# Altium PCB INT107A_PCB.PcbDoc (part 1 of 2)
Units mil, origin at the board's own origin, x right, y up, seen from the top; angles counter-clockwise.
Board outline 2300 x 3400 mil, 4 copper layers (Top Layer, Layer 2 GND, Layer 3 PWR, Bottom Layer), stack 61.634 mil thick; 160 components, 94 nets, 421 pads, 133 vias.
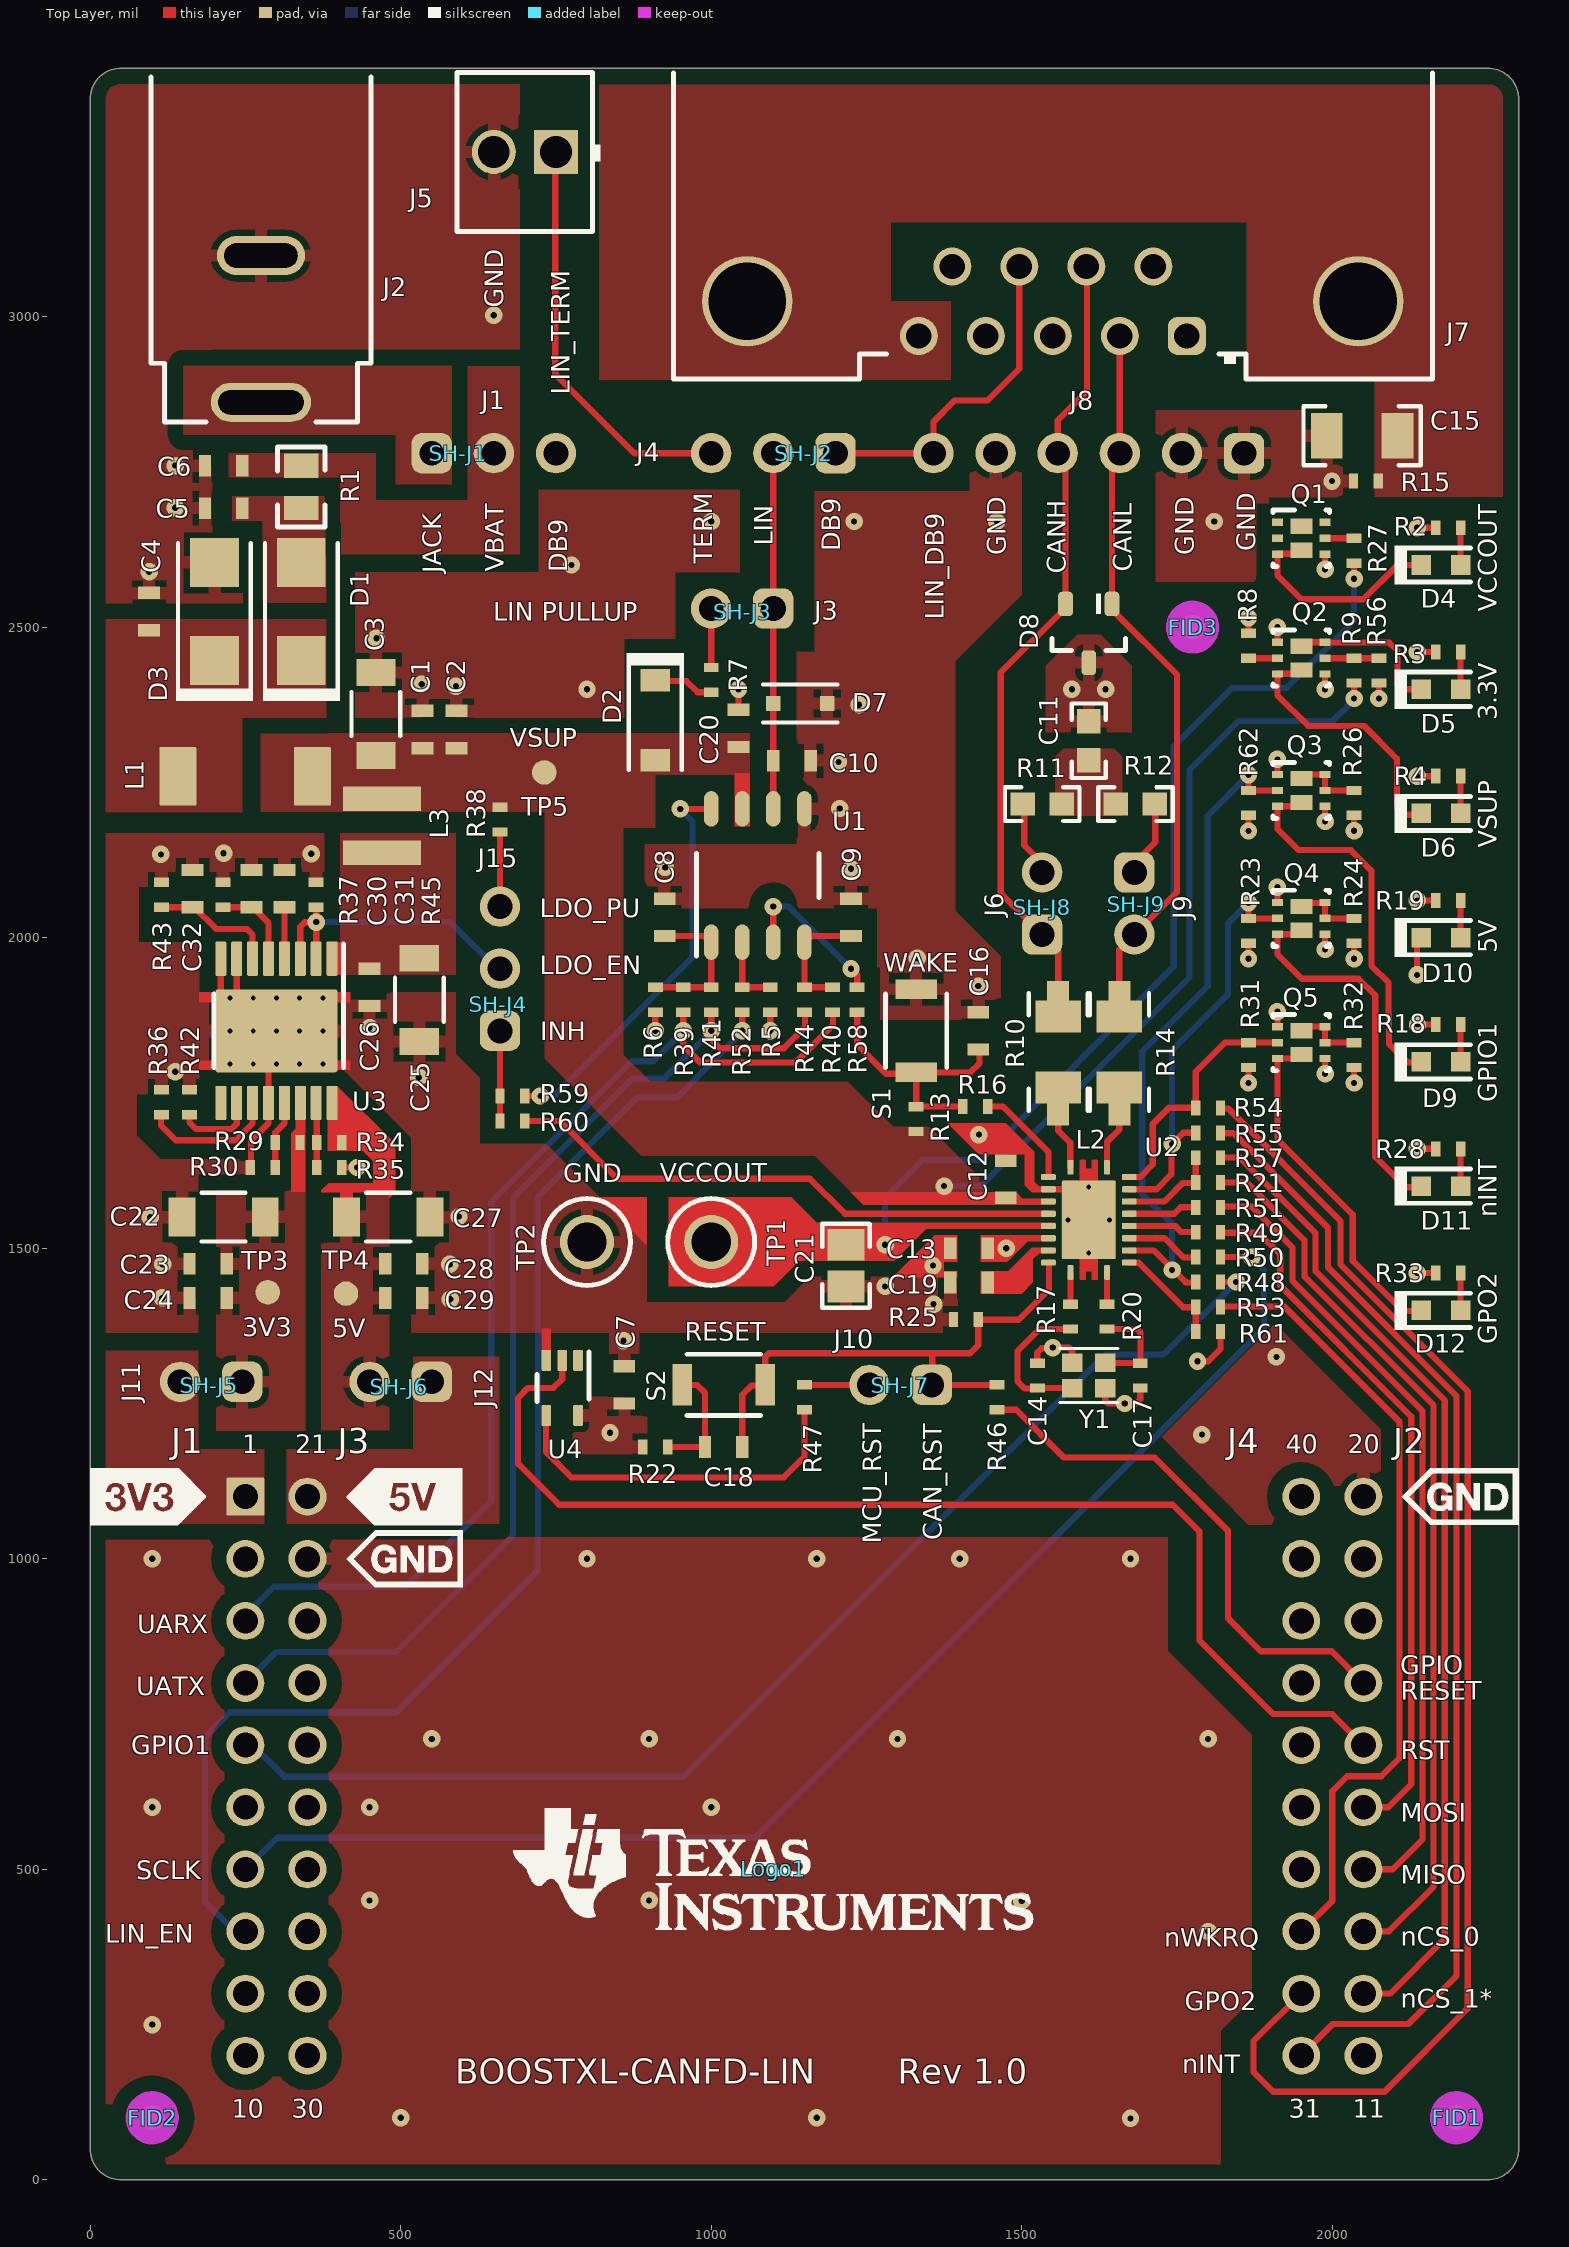
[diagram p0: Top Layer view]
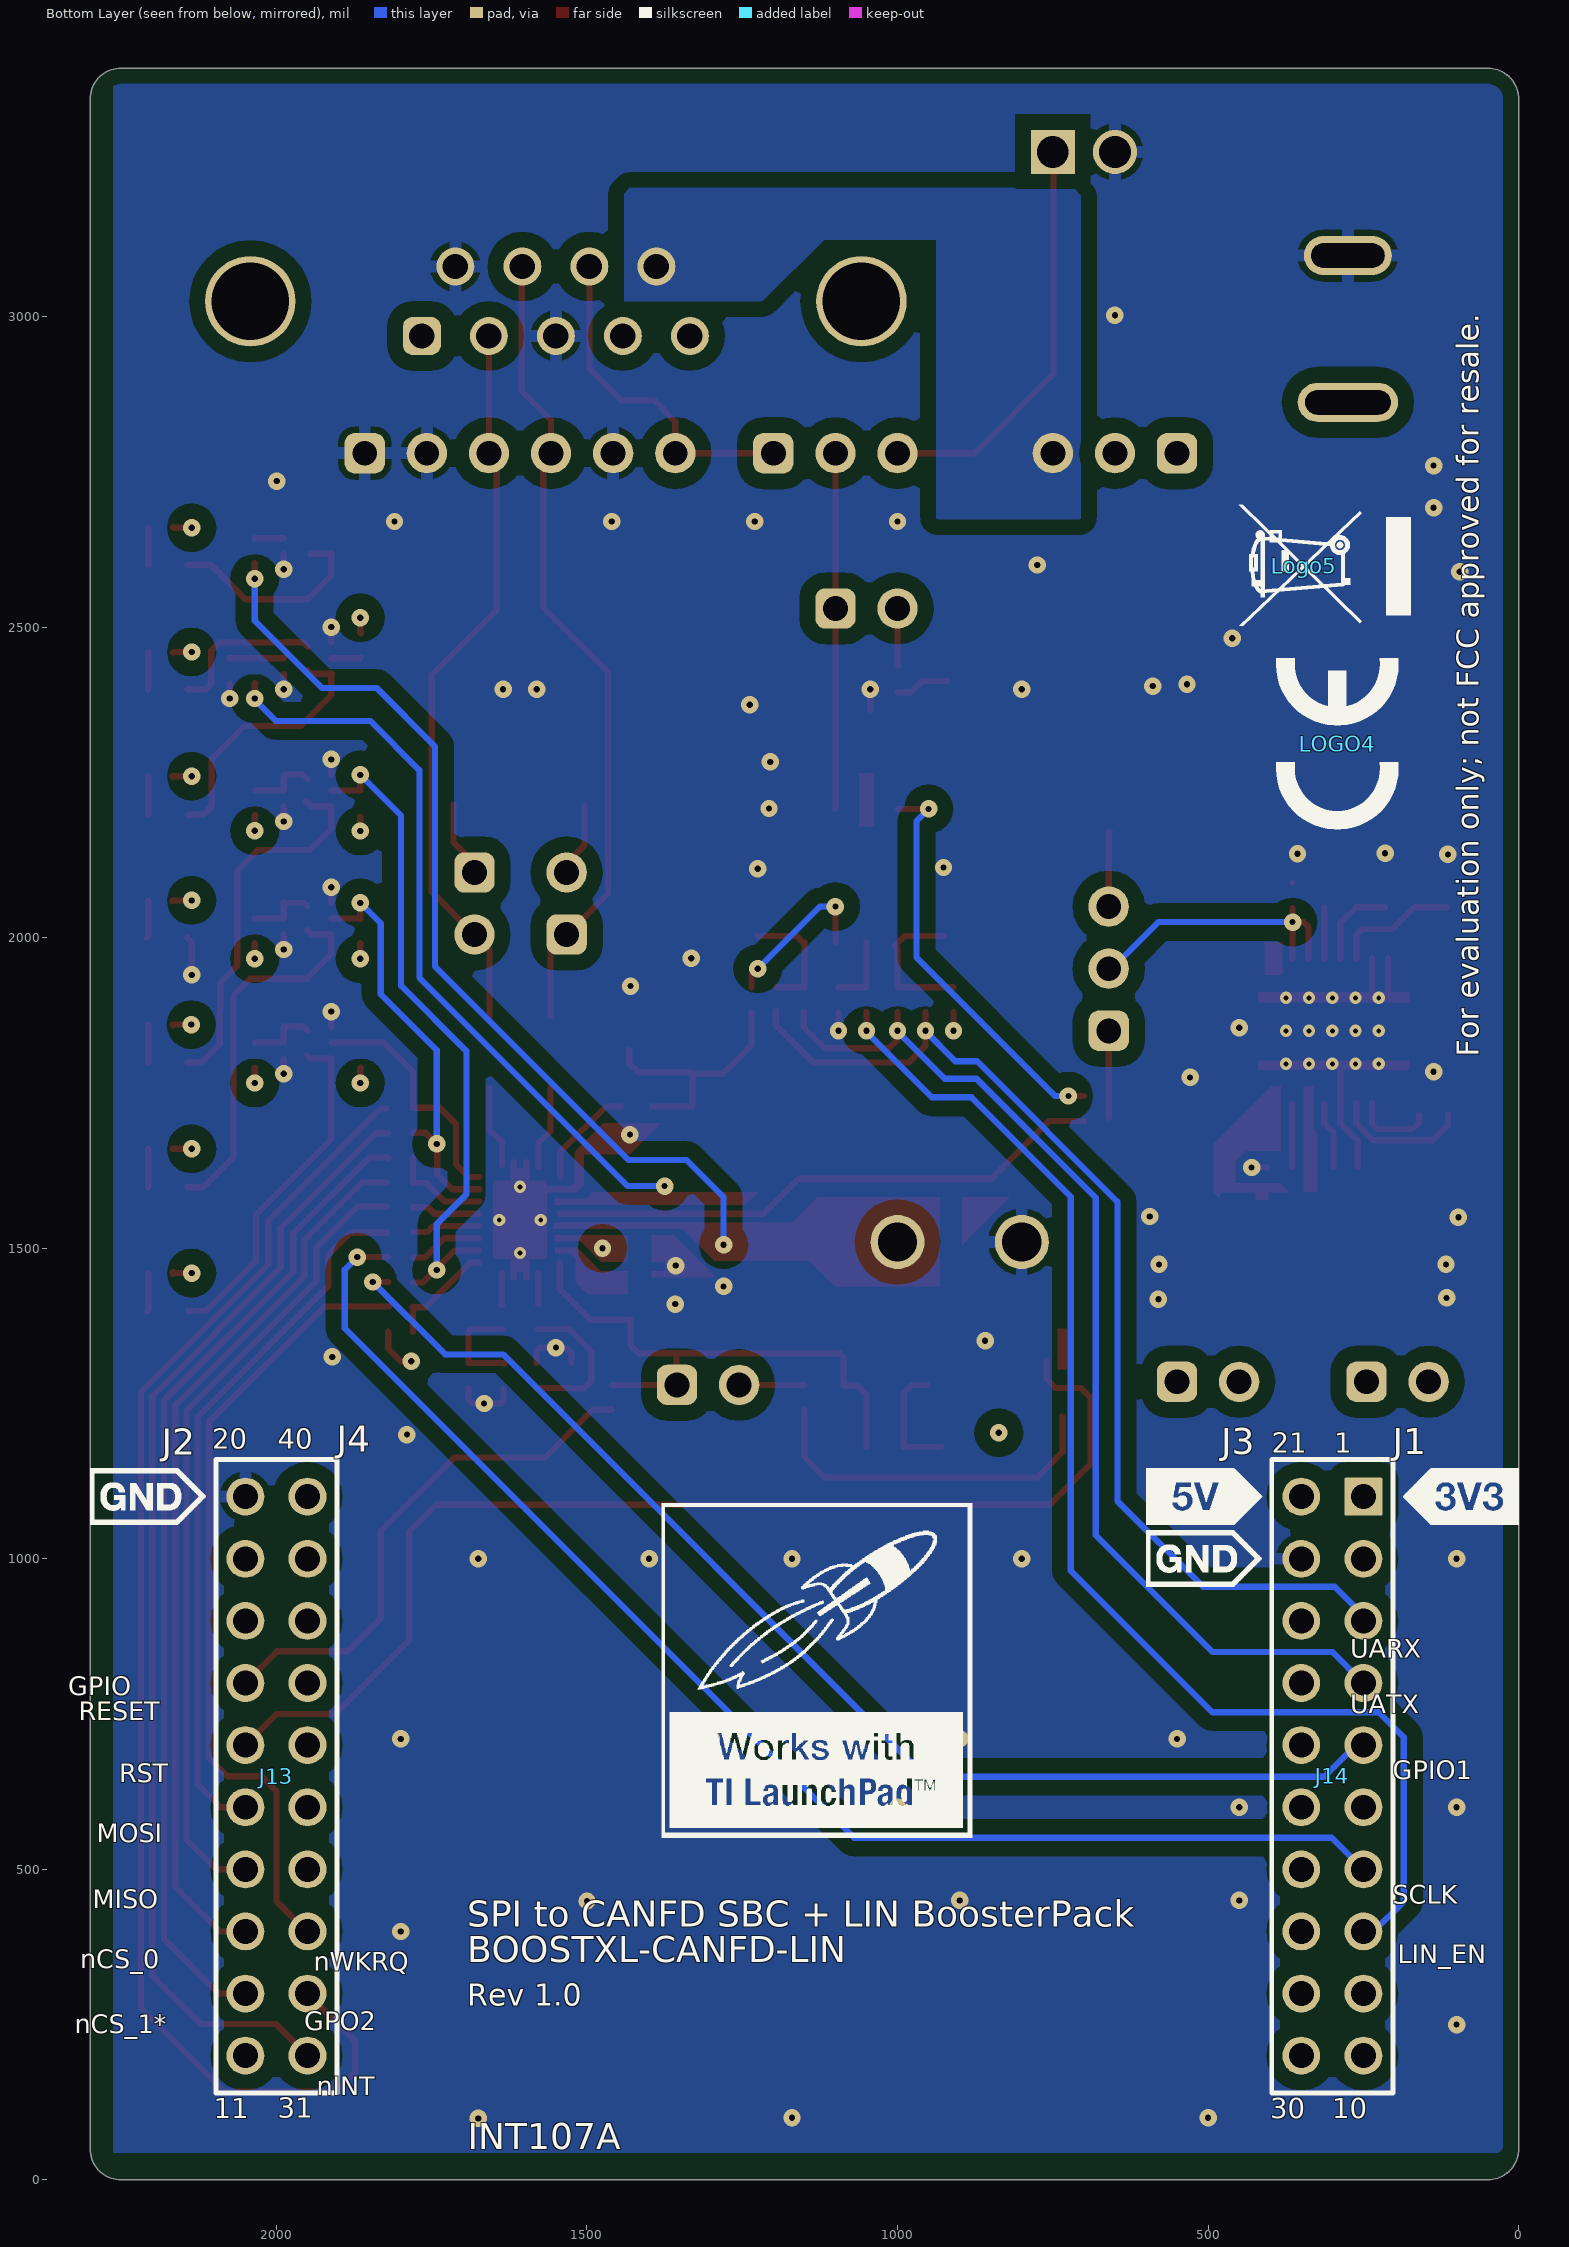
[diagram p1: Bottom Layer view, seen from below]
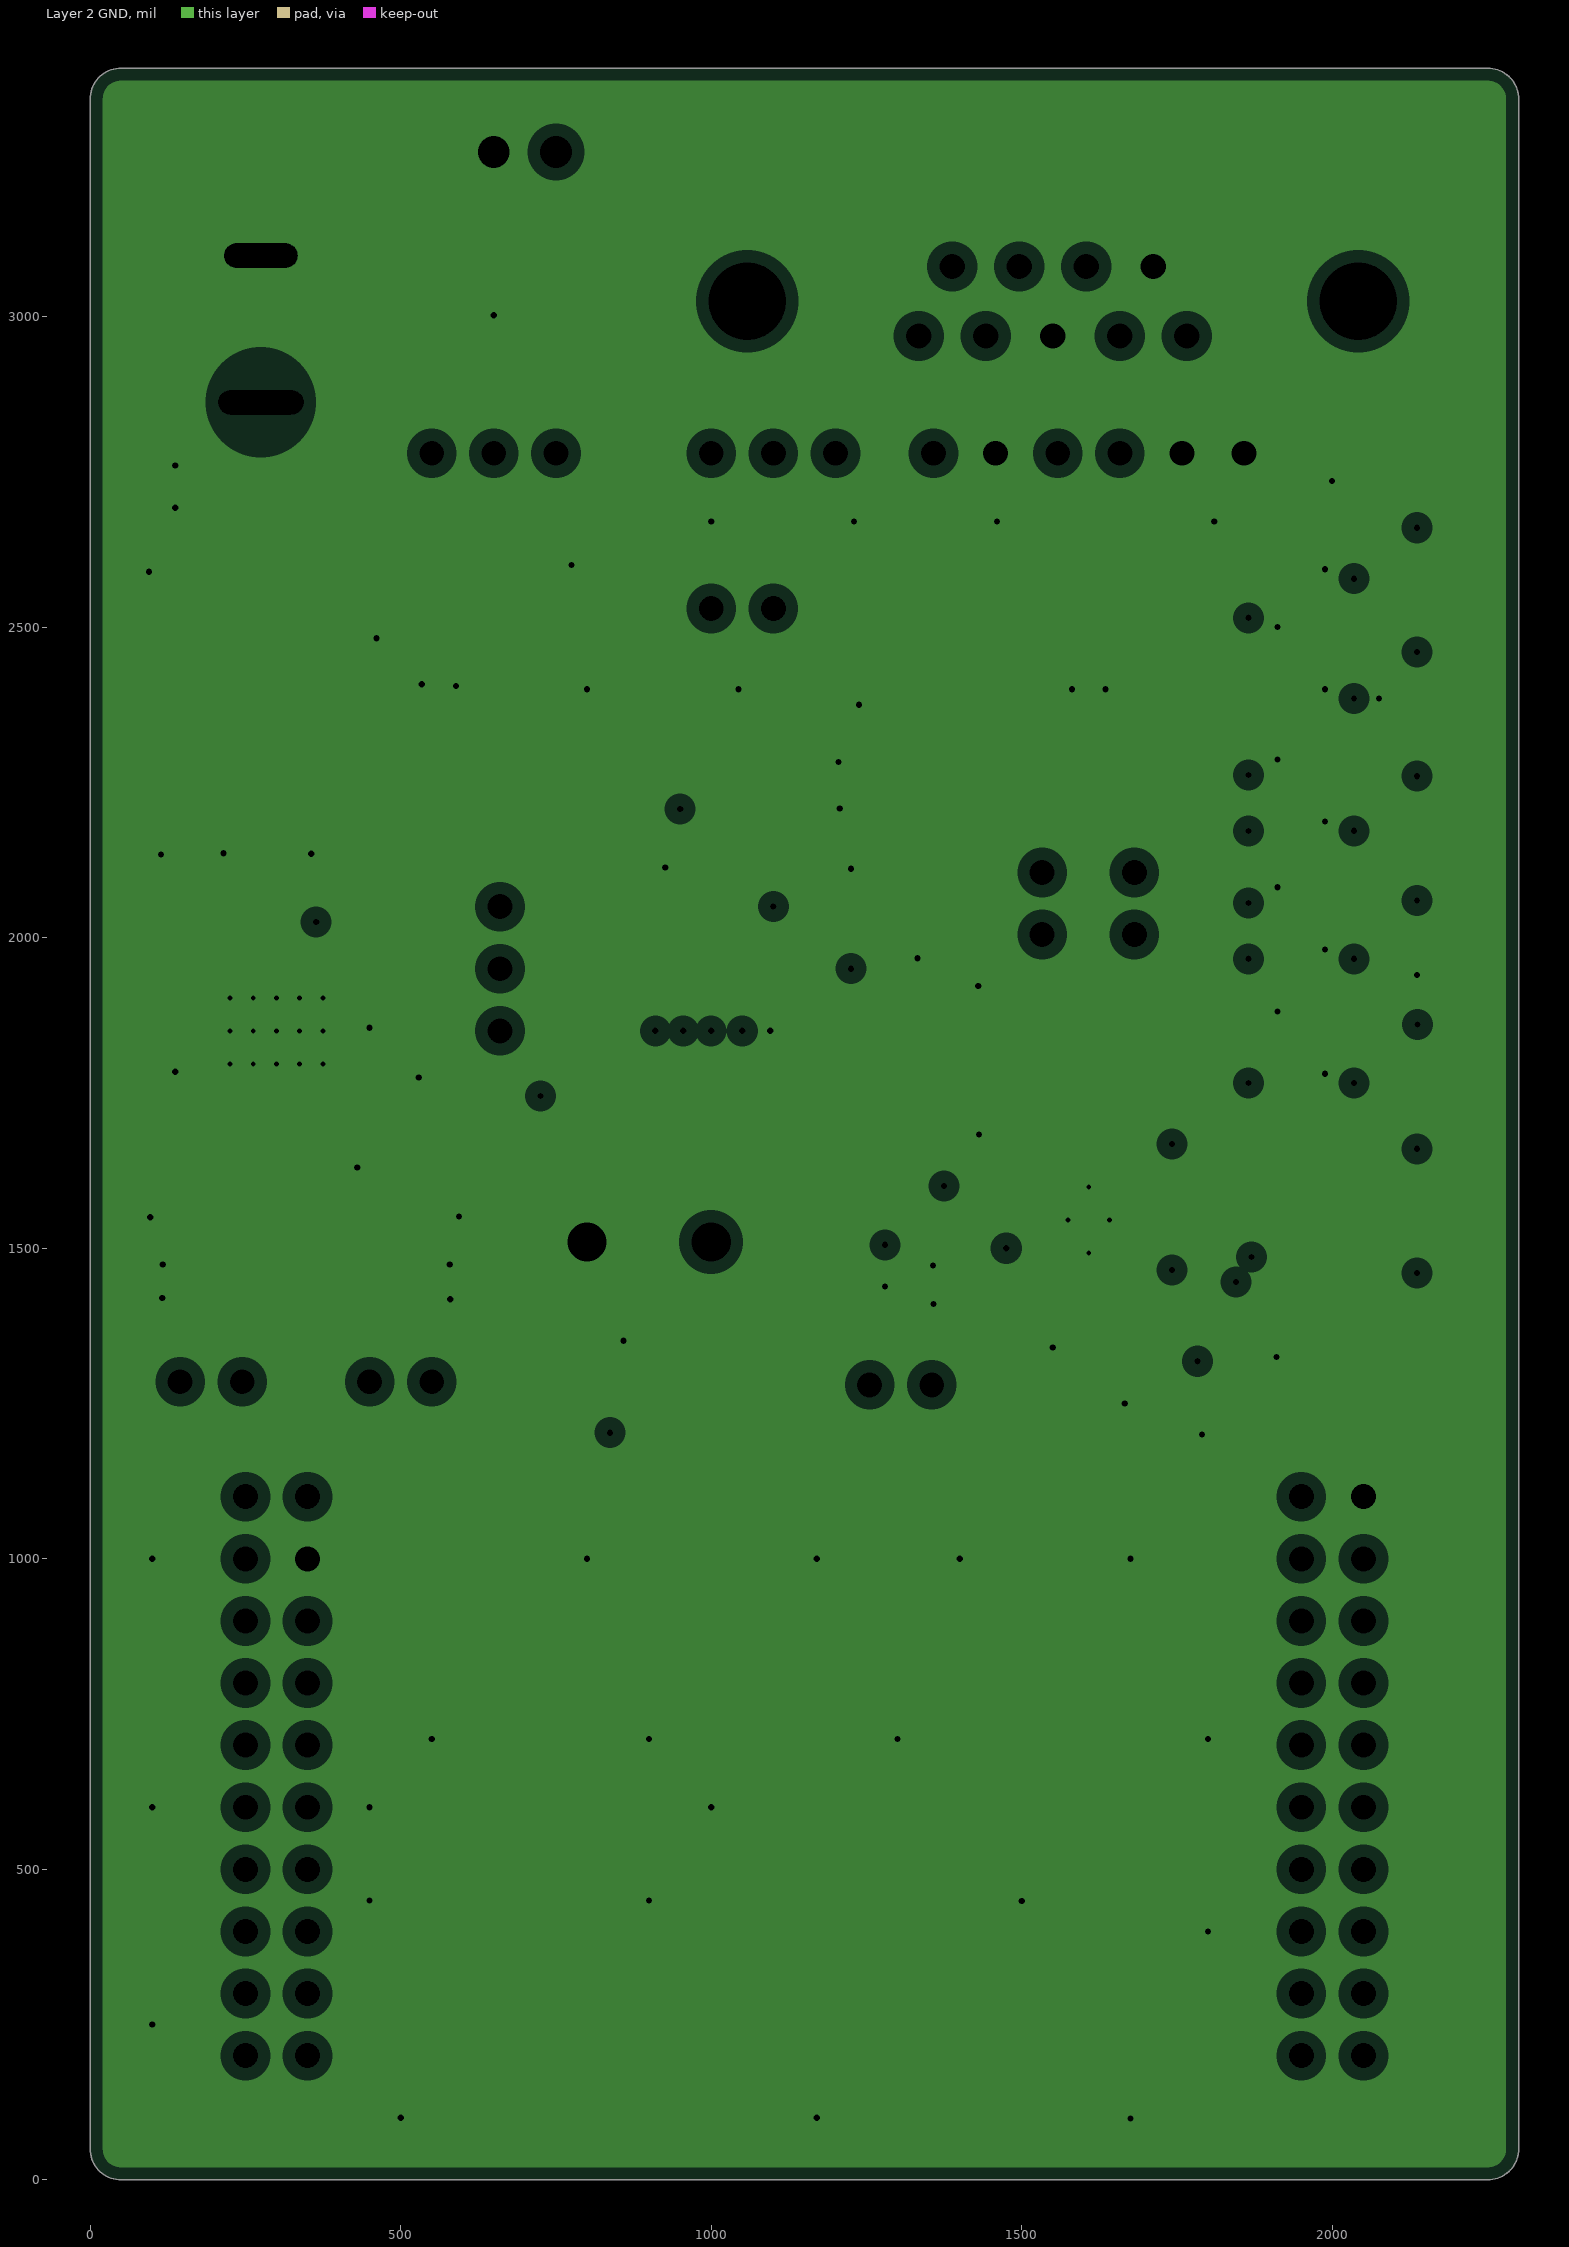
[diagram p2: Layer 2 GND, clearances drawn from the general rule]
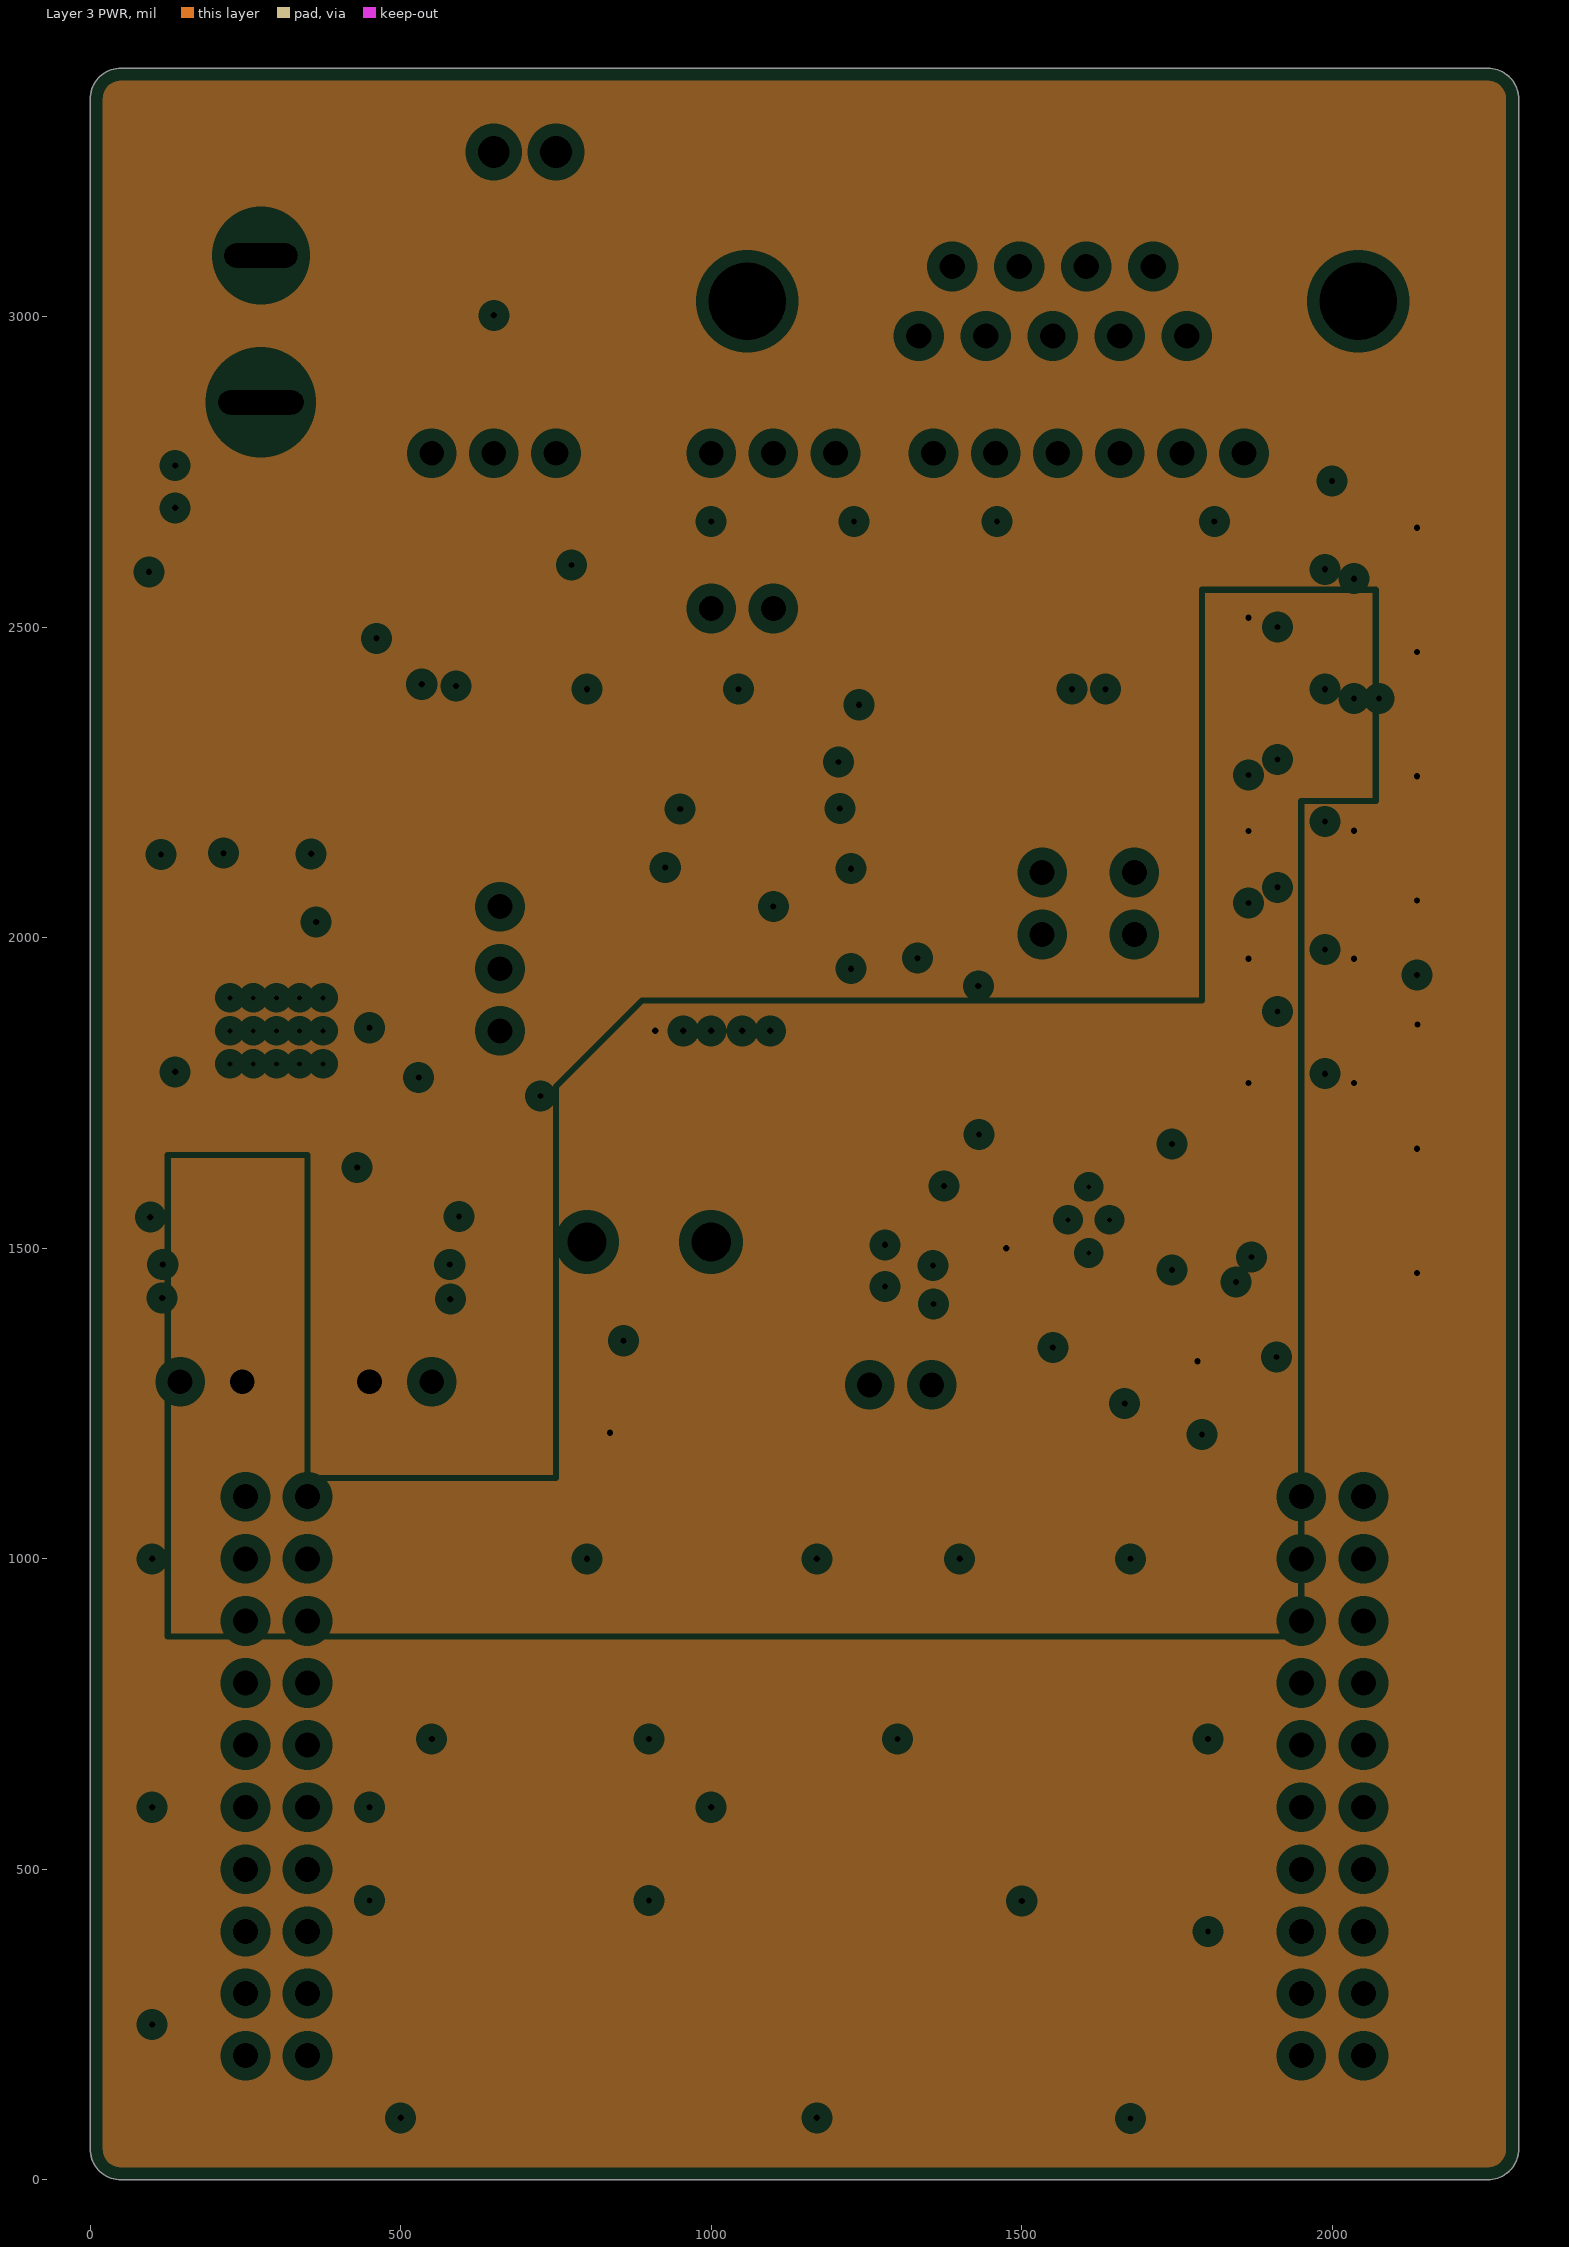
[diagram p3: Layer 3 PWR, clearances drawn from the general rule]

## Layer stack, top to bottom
Top Solder: solder mask 0.4, Solder Resist, Dk 3.5
Top Layer: signal copper 1.4
Dielectric 1: core 6, FR-4, Dk 4.2
Layer 2 GND: plane copper 1.417, net GND
Dielectric 2: prepreg 44, FR-4, Dk 4.2
Layer 3 PWR: plane copper 1.417, net (Multiple Nets)
Dielectric1: core 6, FR-4, Dk 4.2
Bottom Layer: signal copper 1.4
Bottom Solder: solder mask 0.4, Solder Resist, Dk 3.5

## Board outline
50,0 cw(c50,50) 0,50 0,3350 cw(c50,3350) 50,3400 2250,3400 cw(c2250,3350) 2300,3350 2300,50 cw(c2250,50) 2250,0

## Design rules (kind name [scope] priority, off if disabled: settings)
AcuteAngle [All] p1: minimum=4.50000000000000E+0001 checktracksonly=FALSE
AssemblyTestPointUsage [All] p1: valid=2
BoardOutlineClearance BoardOutlineClearance_MountingHoles [OnCopper and InComponentClass('Mounting Holes')] p1: gap=40 ignorepadtopadclearanceinfootprint=FALSE
BoardOutlineClearance BoardOutlineClearance_Poly [OnCopper and IsPoly] p2: gap=25 ignorepadtopadclearanceinfootprint=FALSE
BoardOutlineClearance [OnCopper and Not InComponentClass('Logo') and not InComponentClass('FiducialMark') and not InRegion(1000,500,4000,800) and not InPoly] p3: gap=75 ignorepadtopadclearanceinfootprint=FALSE
Clearance Clearance_Keepouts [((IsTrack Or IsArc) And Not InPoly) And IsFree and IsKeepOut vs ((IsTrack Or IsArc) And Not InPoly) And IsFree and IsKeepOut] p1: gap=0 ignorepadtopadclearanceinfootprint=FALSE
Clearance Clearance_Poly [InPolygon] p2: gap=25 ignorepadtopadclearanceinfootprint=FALSE except(0: Arc-Hole Track-Hole SMDPad-Hole THPad-Hole Via-Hole Fill-Hole Poly-Hole Region-Hole Text-Hole)
Clearance Clearance_Fiducials [HasFootprint('Fiducial10-20')] p3: gap=7.87 ignorepadtopadclearanceinfootprint=TRUE except(0: Arc-SMDPad Track-SMDPad)
Clearance [All] p4: gap=7.87 ignorepadtopadclearanceinfootprint=TRUE except(0: Arc-Hole Track-Hole SMDPad-Hole THPad-Hole Via-Hole Fill-Hole Poly-Hole Region-Hole Text-Hole)
ComponentClearance CANL_Choke_Resistor [InComponent('L2') vs InComponent('R14')] p1: gap=0 collisioncheckmode=3 verticalgap=0 showdistances=FALSE
ComponentClearance CANH_Choke_Resistor [InComponent('L2') vs InComponent('R10')] p2: gap=0 collisioncheckmode=3 verticalgap=0 showdistances=FALSE
ComponentClearance ComponentClearance_MountingHoles_FiducialMarks [InComponentClass('Mounting Holes') vs InComponentClass('FiducialMark')] p3: gap=50 collisioncheckmode=3 verticalgap=10 showdistances=FALSE
ComponentClearance ComponentClearance_Shunt [InComponentClass('Header') vs InComponentClass('Shunt')] p4: gap=0 collisioncheckmode=3 verticalgap=0 showdistances=FALSE
ComponentClearance ComponentClearance_Logo [InComponentClass('Logo')] p5: gap=50 collisioncheckmode=3 verticalgap=10 showdistances=FALSE
ComponentClearance ComponentClearance_ScrewToNut [(HasFootprint('NY PMS 440 0025 PH')) vs (HasFootprint('Keystone_1902C'))] p6: gap=5 collisioncheckmode=3 verticalgap=10 showdistances=FALSE
ComponentClearance ComponentClearance_MountingHoles [InComponentClass('Mounting Holes')] p7: gap=250 collisioncheckmode=3 verticalgap=100000 showdistances=FALSE
ComponentClearance ComponentClearance_SmallPassives [HasFootprint('0201*') or HasFootprint('0402*') or HasFootprint('0508') or HasFootprint('0603*') or HasFootprint('0612') or HasFootprint('0805*') or HasFootprint('0815*') or HasFootprint('0830*') or HasFootprint('1206*') or HasFootprint('1210*') or HasFootprint('1808*') or HasFootprint('1812*') or HasFootprint('1825*') or HasFootprint('2010*') or HasFootprint('2220*') or HasFootprint('2225*') or HasFootprint('2512*') or HasFootprint('2728*') or HasFootprint('3518*') vs HasFootprint('0201*') or HasFootprint('0402*') or HasFootprint('0508') or HasFootprint('0603*') or HasFootprint('0612') or HasFootprint('0805*') or HasFootprint('0815*') or HasFootprint('0830*') or HasFootprint('1206*') or HasFootprint('1210*') or HasFootprint('1808*') or HasFootprint('1812*') or HasFootprint('1825*') or HasFootprint('2010*') or HasFootprint('2220*') or HasFootprint('2225*') or HasFootprint('2512*') or HasFootprint('2728*') or HasFootprint('3518*')] p8: gap=14.96 collisioncheckmode=3 verticalgap=10 showdistances=FALSE
ComponentClearance ComponentClearance_THtoSMT [IsThruComponent vs IsSMTComponent] p9: gap=40 collisioncheckmode=3 verticalgap=30 showdistances=FALSE
ComponentClearance ComponentClearance_THtoTH [IsThruComponent vs IsThruComponent] p10: gap=40 collisioncheckmode=3 verticalgap=30 showdistances=FALSE
ComponentClearance [All] p11: gap=30 collisioncheckmode=3 verticalgap=10 showdistances=FALSE
DiffPairsRouting [All] p1: maxlimit=100 minlimit=10 mostfreqgap=10 toplayer_minwidth=15 toplayer_maxwidth=15 toplayer_prefwidth=15 bottomlayer_minwidth=15 bottomlayer_maxwidth=15 bottomlayer_prefwidth=15 maxuncoupledlength=1000
FabricationTestPointUsage TestPointUsage [All] p1: valid=2 allowmultiple=FALSE
FabricationTestpoint Testpoint [All] p1: side=3 testpointundercomponent=TRUE minsize=40 maxsize=100 preferedsize=60 minholesize=0 maxholesize=40 preferedholesize=32 testpointgrid=1 allowsidetop=TRUE allowsidebottom=TRUE usegrid=TRUE gridtolerance=0.01
FanoutControl Fanout_LCC [IsLCC] p1: bgadir=Out bgaviamode=Centered fanoutstyle=Auto fanoutdirection=Alternating viagrid=1 // Fanout_LCC (Default Rule)
FanoutControl Fanout_BGA [IsBGA] p2: bgadir=Out bgaviamode=Centered fanoutstyle=Auto fanoutdirection=Alternating viagrid=1 // Fanout_BGA (Default Rule)
FanoutControl Fanout_Default [All] p4: bgadir=Out bgaviamode=Centered fanoutstyle=Auto fanoutdirection=Alternating viagrid=1 // Fanout_Default (Default Rule)
FanoutControl Fanout_Small [(CompPinCount < 5)] p5: bgadir=Out bgaviamode=Centered fanoutstyle=Auto fanoutdirection=OutThenIn viagrid=1 // Fanout_Small (Default Rule)
HoleSize [All] p1: absolutevalues=TRUE maxlimit=251 minlimit=7.87 maxpercent=80.000 minpercent=20.000
MinimumAnnularRing MinimumAnnularRing_ThermalPadVias [IsVia and InAnyComponent] p1: minimumring=5.9
MinimumAnnularRing [All] p2: minimumring=5.9
MinimumSolderMaskSliver MinimumSolderMaskSliver_Logo [InComponentClass('Logo') vs InComponentClass('Logo')] p1: minsoldermaskwidth=0.7
MinimumSolderMaskSliver [All] p2: minsoldermaskwidth=3.94
PlaneClearance [All] p1: clearance=20
PlaneConnect [All] p1: planeconnectstyle=Relief reliefexpansion=10 reliefentries=4 reliefconductorwidth=10 reliefairgap=10
PolygonConnect PolygonConnect_Testpoint [HasFootprint('TP_SM_1MM')] p1: connectstyle=Direct reliefconductorwidth=10 reliefentries=4 polygonreliefangle="90 Angle" airgapwidth=10
PolygonConnect PolygonConnect_GND [InNet('GND')] p2: thpad.connectstyle=Relief thpad.reliefconductorwidth=20 thpad.reliefentries=4 thpad.polygonreliefangle="90 Angle" thpad.airgapwidth=10 smdpad.connectstyle=Relief smdpad.reliefconductorwidth=20 smdpad.reliefentries=4 smdpad.polygonreliefangle="90 Angle" smdpad.airgapwidth=10 via.connectstyle=Direct via.reliefconductorwidth=10 via.reliefentries=4 via.polygonreliefangle="90 Angle" via.airgapwidth=10
PolygonConnect PolygonConnect_3V3 [InNet('3V3')] p3: thpad.connectstyle=Relief thpad.reliefconductorwidth=20 thpad.reliefentries=4 thpad.polygonreliefangle="90 Angle" thpad.airgapwidth=10 smdpad.connectstyle=Relief smdpad.reliefconductorwidth=20 smdpad.reliefentries=4 smdpad.polygonreliefangle="90 Angle" smdpad.airgapwidth=10 via.connectstyle=Direct via.reliefconductorwidth=10 via.reliefentries=4 via.polygonreliefangle="90 Angle" via.airgapwidth=10
PolygonConnect PolygonConnect_5V0 [InNet('5V0')] p4: thpad.connectstyle=Relief thpad.reliefconductorwidth=20 thpad.reliefentries=4 thpad.polygonreliefangle="90 Angle" thpad.airgapwidth=10 smdpad.connectstyle=Relief smdpad.reliefconductorwidth=20 smdpad.reliefentries=4 smdpad.polygonreliefangle="90 Angle" smdpad.airgapwidth=10 via.connectstyle=Direct via.reliefconductorwidth=10 via.reliefentries=4 via.polygonreliefangle="90 Angle" via.airgapwidth=10
PolygonConnect [All] p5: connectstyle=Direct reliefconductorwidth=20 reliefentries=4 polygonreliefangle="90 Angle" airgapwidth=10
RoutingVias ThermalPadVias [IsVia and InAnyComponent] p1: holewidth=7.87 width=19.68 viastyle="Through Hole" minholewidth=7.87 minwidth=19.68 maxholewidth=12.99 maxwidth=30
RoutingVias [All] p2: holewidth=16 width=34 viastyle="Through Hole" minholewidth=7.87 minwidth=19 maxholewidth=40 maxwidth=65
SilkToBoardRegionClearance [Not ((IsComment or IsDesignator) And (Hide <> 'False')) and not InRegion(1000,500,4000,800)] p1:
SilkToSilkClearance SilkToSilkClearance_Pb-FreeLogo [(HasFootprint('Pb-Free_Overlay_Medium') OR HasFootprint('Pb-Free_Overlay_Small')) vs (HasFootprint('Pb-Free_Overlay_Medium') OR HasFootprint('Pb-Free_Overlay_Small'))] p1: silktosilkclearance=0
SilkToSilkClearance [All] p2: silktosilkclearance=3
SilkToSolderMaskClearance SilkToComponentPadClearance [IsPad and InAnycomponent] p1: minsilkscreentomaskgap=5 clearancetoexposedcopper=TRUE
SilkToSolderMaskClearance "Silk to Solder Mask Opening" [All] p2: minsilkscreentomaskgap=2 clearancetoexposedcopper=FALSE
SolderMaskExpansion [All] p1: expansion=1.97
Width [All] p1: maxlimit=100 minlimit=6 preferedwidth=10 checkconnectedcopper=TRUE
14 further rules are at their usual default settings.

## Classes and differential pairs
component class Shunt: SH-J1 SH-J2 SH-J3 SH-J4 SH-J5 SH-J6 SH-J7 SH-J8 SH-J9
component class Header: J1 J3 J4 J6 J8 J9 J10 J11 J12 J15
component class INT107A_Schematic: C1 C2 C3 C4 C5 C6 C7 C8 C9 C10 C11 C12 C13 C14 C15 C16 C17 C18 C19 C20 C21 C22 C23 C24 C25 C26 C27 C28 C29 C30 C31 C32 D1 D2 D3 D4 D5 D6 D7 D8 D9 D10 D11 D12 J1 J2 J3 J4 J5 J6 J7 J8 J9 J10 J11 J12 J13 J14 J15 L1 L2 L3 Q1 Q2 Q3 Q4 Q5 R1 R2 R3 R4 R5 R6 R7 R8 R9 R10 R11 R12 R13 R14 R15 R16 R17 R18 R19 R20 R21 R22 R23 R24 R25 R26 R27 R28 R29 R30 R31 R32 R33 R34 R35 R36 R37 R38 R39 R40 R41 R42 R43 R44 R45 R46 R47 R48 R49 R50 R51 R52 R53 R54 R55 R56 R57 R58 R59 R60 R61 R62 S1 S2 TP1 TP2 TP3 TP4 TP5 U1 U2 U3 U4 Y1
component class Logo: Logo1
component class INT107A_Hardware: FID1 FID2 FID3 Logo1 Logo3 LOGO4 Logo5 SH-J1 SH-J2 SH-J3 SH-J4 SH-J5 SH-J6 SH-J7 SH-J8 SH-J9 ZZ2 ZZ3 ZZ4
component class FiducialMark: FID1 FID2 FID3
component class AssemblyNote: ZZ2 ZZ3 ZZ4

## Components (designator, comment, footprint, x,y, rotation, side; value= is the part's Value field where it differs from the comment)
C1 "CGA3E2X7R1H104K080AA" 0603S 535,2335 r90 top value=0.1uF
C2 "UMK107AB7105KA-T" 0603S 590,2335 r90 top value=1uF
C3 "CL31B106KBHNNNE" 1206_180 460,2360 r90 top value=10uF
C4 "CGA3E2X7R2A102K080AA" 0603S 95,2525 r90 top value=1000pF
C5 "CGA3E2X7R2A102K080AA" 0603S 215,2691.53 r180 top value=1000pF
C6 "CGA3E2X7R2A102K080AA" 0603S 215,2759.65 r180 top value=1000pF
C7 "CGA3E2X7R1H104K080AA" 0603S 860,1280 r90 top value=0.1uF
C8 "CGA3E2NP01H100D080AA" 0603S 925,2032.72 r90 top value=10pF
C9 "CGA3E2NP01H100D080AA" 0603S 1225,2032.72 r90 top value=10pF
C10 "06035A221FAT2A" 0603S 1130,2285 r0 top value=220pF
C11 "06031C472KAT2A" 0603 1607.87,2317 r270 top value=4700pF
C12 "CGA3E2X7R1H104K080AA" 0603S 1474,1611 r90 top value=0.1uF
C13 "CGA3E2X7R1H104K080AA" 0603S 1415,1500 r180 top value=0.1uF
C14 "CC0402DRNPO9BN8R0" 0402S 1525,1295 r90 top value=8pF
C15 "12061C103JAT2A" 1206 2048,2808 r180 top value=0.01uF
C16 "06035A101JAT2A" 0603S 1430,1850 r90 top value=100pF
C17 "CC0402DRNPO9BN8R0" 0402S 1690.75,1295 r270 top value=8pF
C18 "06035A101JAT2A" 0603S 1020,1180 r180 top value=100pF
C19 "C0603C334K4RACTU" 0603S 1415,1445 r180 top value=0.33uF
C20 "CGA3E2X7R1H104K080AA" 0603S 1044,2337 r90 top value=0.1uF
C21 "CL21B106KOQNNNE" 0805 1217,1472 r270 top value=10uF
C22 "C1206C106K4RACTU" 1206_180 215,1550 r0 top value=10uF
C23 "UMK107AB7105KA-T" 0603S 190,1475 r180 top value=1uF
C24 "CGA3E2X7R1H104K080AA" 0603S 190,1420 r180 top value=0.1uF
C25 "CL31B106KBHNNNE" 1206_180 530,1900 r270 top value=10uF
C26 "CGA3E2X7R1H104K080AA" 0603S 450,1920 r270 top value=0.1uF
C27 "C1206C106K4RACTU" 1206_180 480,1550 r180 top value=10uF
C28 "UMK107AB7105KA-T" 0603S 505,1475 r0 top value=1uF
C29 "CGA3E2X7R1H104K080AA" 0603S 505,1420 r0 top value=0.1uF
C30 "GCM188R71C105KA64J" 0603S 260,2079 r90 top value=1uF
C31 "GCM188R71C105KA64J" 0603S 312.79,2079 r90 top value=1uF
C32 "GCM188R71C105KA64J" 0603S 165,2079 r90 top value=1uF
D1 "MBRA140T3G" SMA 340,2525 r90 top value=40V
D2 "1N4148W-TP" SOD-123 910,2350 r270 top value=100V
D3 "3SMAJ5936B-TP" SMA 200,2525 r90 top value=30V
D4 "150060GS75000" WL-SMCW_GREEN 2175,2600 r0 top value=Green
D5 "150060GS75000" WL-SMCW_GREEN 2175,2400 r0 top value=Green
D6 "150060GS75000" WL-SMCW_GREEN 2175,2200 r0 top value=Green
D7 "PESD1LIN,115" SOD-323-Bi 1143.31,2377 r180 top value=15V
D8 "PESD1CAN,215" SOT-23 1607.87,2490 r270 top value=24V
D9 "150060YS75000" WL-SMCW_YELLOW 2175,1800 r0 top value=Yellow
D10 "150060GS75000" WL-SMCW_GREEN 2175,2000 r0 top value=Green
D11 "150060BS75000" WL-SMCW_Blue 2175,1600 r0 top value=Blue
D12 "150060RS75000" WL-SMCW_RED 2175,1400 r0 top value=Red
FID1 "Fiducial" Fiducial10-20 2200,100 r0 top
FID2 "Fiducial" Fiducial10-20 100,100 r0 top
FID3 "Fiducial" Fiducial10-20 1775,2500 r0 top
J1 "TSW-103-07-G-S" TSW-103-07-G-S 650,2780 r0 top
J2 "PJ-037AH" CUI_PJ-037AH 275,2980 r180 top
J3 "TSW-102-07-G-S" TSW-102-07-G-S 1050,2530 r180 top
J4 "TSW-103-07-G-S" TSW-103-07-G-S 1100,2780 r180 top
J5 "OSTVN02A150" On-Shore_OSTVN02A150 700,3265 r180 top
J6 "TSW-102-07-G-S" TSW-102-07-G-S 1532.79,2055 r90 top
J7 "5747840-5" TE_5747840-5 1550,3400 r180 top
J8 "TSW-106-07-G-S" TSW-106-07-G-S 1607.87,2780 r180 top
J9 "TSW-102-07-G-S" TSW-102-07-G-S 1681.21,2055 r270 top
J10 "TSW-102-07-G-S" TSW-102-07-G-S 1305,1280 r180 top
J11 "TSW-102-07-G-S" TSW-102-07-G-S 195,1285 r180 top
J12 "TSW-102-07-G-S" TSW-102-07-G-S 500,1285 r180 top
J13 "SSQ-110-03-T-D" BoosterPack_40pin_J2J4 2000,650 r180 bottom locked
J14 "SSQ-110-03-T-D" BoosterPack_40pin_J1J3 300,650 r180 bottom locked
J15 "TSW-103-07-G-S" TSW-103-07-G-S 660,1950 r90 top
L1 "B82462A4472M000" B82462A4 249.73,2260 r180 top value=4.7uH
L2 "ACT45B-101-2P-TL003" ACT45B 1607.87,1814 r90 top value=100uH
L3 "744025100" WE-TPC_2828 470,2180 r270 top value=10uH
Logo1 "Texas Instruments" TI_Stacked_Overlay_Small 1100,500 r0 top
Logo3 "FCC disclaimer" FCC_disclaimer 5234,390 r180 bottom
LOGO4 "CE Mark" CE_Mark_5mm 292,2312 r90 bottom
Logo5 "WEEE logo" WEEE_Minimum 346,2598 r90 bottom
Q1 "CSD85301Q2" DQK0006B 1950,2643 r0 top value=20V
Q2 "CSD85301Q2" DQK0006B 1950,2450 r0 top value=20V
Q3 "CSD85301Q2" DQK0006B 1950,2237 r0 top value=20V
Q4 "CSD85301Q2" DQK0006B 1950,2031 r0 top value=20V
Q5 "CSD85301Q2" DQK0006B 1950,1831 r0 top value=20V
R1 "5106" 5106 340,2725 r90 top value=0
R2 "RC0402FR-0710KL" 0402S 2186.5,2660 r180 top value=10.0k
R3 "RC0402FR-0710KL" 0402S 2186.5,2460 r180 top value=10.0k
R4 "RC0402FR-074K99L" 0402S 2186.5,2260 r180 top value=4.99k
R5 "RC0402FR-0710KL" 0402S 1095,1900 r90 top value=10.0k
R6 "RC0402FR-0710KL" 0402S 910,1900 r270 top value=10.0k
R7 "CRCW04021K00FKED" 0402S 1000,2415 r270 top value=1.00k
R8 "RC0402FR-0710KL" 0402S 1865,2470 r90 top value=10.0k
R9 "RC1005F104CS" 0402S 2035,2430 r90 top value=100k
R10 "ERJ-8GEY0R00V" 1206 1558.66,1816 r90 top value=0
R11 "RC0603FR-0760R4L" 0603 1532.87,2215 r180 top value=60.4
R12 "RC0603FR-0760R4L" 0603 1682.87,2215 r180 top value=60.4
R13 "ERJ-2RKF3301X" 0402S 1330,1708 r270 top value=3.30k
R14 "ERJ-8GEY0R00V" 1206 1657.09,1816 r90 top value=0
R15 "ERJ-2RKF1004X" 0402S 2054,2735 r0 top value=1.00Meg
R16 "CRCW040233K2FKED" 0402S 1425,1728 r0 top value=33.2k
R17 "RC0402JR-070RL" 0402S 1578.35,1390 r270 top value=0
R18 "RC0402FR-074K99L" 0402S 2186.5,1860 r180 top value=4.99k
R19 "RC0402FR-0710KL" 0402S 2186.5,2060 r180 top value=10.0k
R20 "RC0402JR-070RL" 0402S 1637.4,1390 r270 top value=0
R21 "RC0402JR-070RL" 0402S 1800,1605.65 r180 top value=0
R22 "RC0402FR-071KL" 0402S 910,1180 r180 top value=1.00k
R23 "RC0402FR-0710KL" 0402S 1865,2011 r270 top value=10.0k
R24 "RC0402FR-0710KL" 0402S 2035,2011 r270 top value=10.0k
R25 "RC1005F104CS" 0402S 1410,1385 r0 top value=100k
R26 "RC0402FR-0710KL" 0402S 2035,2217 r270 top value=10.0k
R27 "RC0402FR-0710KL" 0402S 2035,2623 r270 top value=10.0k
R28 "RC0402FR-071KL" 0402S 2186.5,1660 r180 top value=1.00k
R29 "RC0402FR-0710KL" 0402S 318,1670 r0 top value=10.0k
R30 "CRCW04025K90FKED" 0402S 278,1630 r180 top value=5.90k
R31 "RC0402FR-0710KL" 0402S 1865,1811 r270 top value=10.0k
R32 "RC0402FR-0710KL" 0402S 2035,1811 r270 top value=10.0k
R33 "RC0402FR-074K99L" 0402S 2186.5,1460 r180 top value=4.99k
R34 "RC0402FR-0710KL" 0402S 385,1670 r180 top value=10.0k
R35 "ERJ-2RKF3301X" 0402S 385,1630 r180 top value=3.30k
R36 "RC0402JR-070RL" 0402S 115,1735 r90 top value=0
R37 "CRCW04021K50FKED" 0402S 214,2069 r270 top value=1.50k
R38 "RC0402FR-0710KL" 0402S 660,2190 r270 top value=10.0k
R39 "RC0402JR-070RL" 0402S 955,1900 r90 top value=0
R40 "RC0402JR-070RL" 0402S 1195,1900 r90 top value=0
R41 "RC0402JR-070RL" 0402S 1000,1900 r90 top value=0
R42 "RC0402JR-070RL" 0402S 160,1735 r90 top value=0
R43 "CRCW04021K50FKED" 0402S 115,2069 r270 top value=1.50k
R44 "RC0402JR-070RL" 0402S 1150,1900 r90 top value=0
R45 "RC1005F104CS" 0402S 363.98,2069 r90 top value=100k
R46 "RC0402JR-070RL" 0402S 1460,1260 r90 top value=0
R47 "RC0402FR-0710KL" 0402S 1150,1260 r270 top value=10.0k
R48 "RC0402JR-070RL" 0402S 1800,1445.65 r0 top value=0
R49 "RC0402JR-070RL" 0402S 1800,1525.65 r180 top value=0
R50 "RC0402JR-070RL" 0402S 1800,1485.65 r0 top value=0
R51 "RC0402JR-070RL" 0402S 1800,1565.65 r180 top value=0
R52 "RC0402JR-070RL" 0402S 1050,1900 r270 top value=0
R53 "RC0402JR-070RL" 0402S 1800,1405.65 r0 top value=0
R54 "RC0402JR-070RL" 0402S 1800,1725.65 r0 top value=0
R55 "RC0402JR-070RL" 0402S 1800,1685.65 r0 top value=0
R56 "CRCW040217K4FKED" 0402S 2075,2430 r90 top value=17.4k
R57 "RC0402JR-070RL" 0402S 1800,1645.65 r180 top value=0
R58 "CRCW040233K2FKED" 0402S 1235,1900 r270 top value=33.2k
R59 "RC0402JR-070RL" 0402S 680,1745 r180 top value=0
R60 "RC0402JR-070RL" 0402S 680,1705 r0 top value=0
R61 "RC0402FR-0710KL" 0402S 1800,1365.65 r0 top value=10.0k
R62 "RC0402FR-0710KL" 0402S 1865,2217 r270 top value=10.0k
S1 "B3U-1000P" SW_B3U-1000P 1330,1850 r270 top
S2 "B3U-1000P" SW_B3U-1000P 1020,1280 r0 top
SH-J1 "60900213421" Wurth_60900213421 593,2780 r180 top
SH-J2 "60900213421" Wurth_60900213421 1149.13,2780 r180 top
SH-J3 "60900213421" Wurth_60900213421 1051,2525 r180 top
SH-J4 "60900213421" Wurth_60900213421 657,1893 r270 top
SH-J5 "60900213421" Wurth_60900213421 191.73,1279 r180 top
SH-J6 "60900213421" Wurth_60900213421 498,1277 r180 top
SH-J7 "60900213421" Wurth_60900213421 1304,1279 r180 top
SH-J8 "60900213421" Wurth_60900213421 1532.79,2049 r90 top
SH-J9 "60900213421" Wurth_60900213421 1684,2054 r90 top
TP1 "5010" Keystone5010 1000,1510 r90 top
TP2 "5011" Keystone5011 800,1510 r90 top
TP3 "TP_SM_1MM" TP_SM_1MM 286,1429 r90 top
TP4 "TP_SM_1MM" TP_SM_1MM 412,1427 r90 top
TP5 "TP_SM_1MM" TP_SM_1MM 731,2266 r90 top
U1 "TLIN2029DQ1" D0008A_N 1075,2100 r90 top
U2 "TCAN4550RGYRQ1" RGY0020C 1607.87,1545.65 r180 top
U3 "TPS7B7702QPWPRQ1" PWP0016J_N 300,1850 r270 top
U4 "SN74AUP1T04DCKR" DCK0005A_N 760,1275 r270 top
Y1 "NX2016SA-40M-STD-CZS-3" XTAL_NX2016SA 1607.87,1295 r0 top
ZZ2 "These assemblies are ESD sensitive, ESD precautions shall be observed." AssemblyNote 232,4492.11 r0 top
ZZ3 "These assemblies must be clean and free from flux and all contaminants. Use of no clean flux is not acceptable." AssemblyNote 232,4403.56 r0 top
ZZ4 "These assemblies must comply with workmanship standards IPC-A-610 Class 2, unless otherwise specified." AssemblyNote 232,4315 r0 top

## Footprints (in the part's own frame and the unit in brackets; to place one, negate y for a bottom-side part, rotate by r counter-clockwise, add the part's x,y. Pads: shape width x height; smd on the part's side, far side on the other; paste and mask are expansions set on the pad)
0402S [mil] "Based on C0402S footprint from PADS legacy"
  rect 15x24 smd: 1(-20,0) 2(20,0)
  body extent -22,-12 22,12, height 24
0603 [mm] "0603 from SM-752 data"
  rect 1x0.95 smd: 1(-0.8,0) 2(0.8,0)
  silkscreen extent -1.52,-0.69 1.52,0.69, body extent -0.87,-0.47 0.87,0.47, height 1
0603S [mil]
  rect 20x35 smd: 1(-30,0) 2(30,0)
  body extent -34,-19 34,19, height 39
0805 [mm] "0805 from SM-752 data"
  rect 1.3x1.5 smd: 1(-0.85,0) 2(0.85,0)
  silkscreen extent -1.72,-0.97 1.72,0.97, body extent -1.1,-0.72 1.1,0.72, height 1.45
1206 [mm] "1206 from SM-752 data"
  rect 1.3x1.85 smd: 1(-1.45,0) 2(1.45,0)
  silkscreen extent -2.4,-1.21 2.4,1.21, body extent -1.7,-0.9 1.7,0.9, height 1.35
1206_180 [mm] "1206_180"
  rect 1.1x1.6 smd: 1(-1.7,0) 2(1.7,0)
  silkscreen extent -0.9,-1 0.9,1, body extent -1.75,-0.95 1.75,0.95, height 1.8
5106 [mm] "Keystone"
  rect 0.99x1.4 smd: 1(-0.85,0) 2(0.88,0)
  silkscreen extent -1.63,-0.97 1.65,0.97, body extent -1.06,-0.69 1.06,0.69, height 0.84
ACT45B [mm] "SMD, 4-Leads, Body 4.7 x 3.7 mm"
  rect 1.35x0.9 smd: 1(-2.275,1.25) 2(-2.275,-1.25) 3(2.275,-1.25) 4(2.275,1.25)
  body extent -2.35,-1.7 2.35,1.7, height 3
AssemblyNote [mil] "Assembly Note"
B82462A4 [mm] "SMD, 2-Leads, Body 6x6mm"
  rrect7% 1.5x2.4 smd: 1(-2.75,0) 2(2.75,0)
  body extent -3.1,-3.05 3.1,2.94, height 3
BoosterPack_40pin_J1J3 [mm] "Receptacle, 2.54mm, 10x2, TH"
  rrect6% 1.55x1.55 hole 1.02: 1(1.27,11.43)
  round 1.55 hole 1.02: 2(1.27,8.89) 3(1.27,6.35) 4(1.27,3.81) 5(1.27,1.27) 6(1.27,-1.27) 7(1.27,-3.81) 8(1.27,-6.35) 9(1.27,-8.89) 10(1.27,-11.43) 21(-1.27,11.43) 22(-1.27,8.89) 23(-1.27,6.35) 24(-1.27,3.81) 25(-1.27,1.27) 26(-1.27,-1.27) 27(-1.27,-3.81) 28(-1.27,-6.35) 29(-1.27,-8.89) 30(-1.27,-11.43)
  silkscreen extent -7.62,-12.95 7.62,12.95, body extent -2.48,-12.95 2.48,12.95, height 8.51
BoosterPack_40pin_J2J4 [mm] "Receptacle, 2.54mm, 10x2, TH"
  round 1.55 hole 1.02: 11(-1.27,-11.43) 12(-1.27,-8.89) 13(-1.27,-6.35) 14(-1.27,-3.81) 15(-1.27,-1.27) 16(-1.27,1.27) 17(-1.27,3.81) 18(-1.27,6.35) 19(-1.27,8.89) 20(-1.27,11.43) 31(1.27,-11.43) 32(1.27,-8.89) 33(1.27,-6.35) 34(1.27,-3.81) 35(1.27,-1.27) 36(1.27,1.27) 37(1.27,3.81) 38(1.27,6.35) 39(1.27,8.89) 40(1.27,11.43)
  silkscreen extent -7.62,-12.95 2.48,12.95, body extent -2.48,-12.95 2.48,12.95, height 8.51
CE_Mark_5mm [mil] "Minimum text height for CE Mark"
  silkscreen extent -138,-98 138,98
CUI_PJ-037AH [mm] "Power Jack, 2mm, R/A, TH"
  oval 4.1x1.6 hole 1 slot 3.5 at 0 deg: 1(0,3)
  oval 3.6x1.6 hole 1 slot 3 at 0 deg: 2(0,-3)
  silkscreen extent -4.5,-10.3 4.5,3.8, body extent -4.5,-10.7 4.5,3.8, height 11
D0008A_N [mm] "SOIC, 8-Leads, Body 4.9x3.9mm, Pitch 1.27mm, IPC Medium Density"
  oval 1.45x0.6 smd: 1(-2.725,1.905) 2(-2.725,0.635) 3(-2.725,-0.635) 4(-2.725,-1.905) 5(2.725,-1.905) 6(2.725,-0.635) 7(2.725,0.635) 8(2.725,1.905)
  silkscreen extent -3.3,-2.5 0.9,2.5, body extent -3,-2.45 3,2.45, height 1.63
DCK0005A_N [mm] "SOT353, 5-Leads, Body 2x1.3mm, Pitch 0.65mm, Lead Span 2.1mm, IPC Medium Density"
  rrect25% 0.85x0.4 smd: 1(-1.125,0.65) 2(-1.125,0) 3(-1.125,-0.65) 4(1.125,-0.65) 5(1.125,0.65)
  silkscreen extent -1.48,-1.02 0.55,1.1, body extent -1.14,-1 1.14,1, height 0.95
DQK0006B [mm] "TI"
  rect 0.45x0.3 smd: 1(-0.975,0.65) 2(-0.975,0) 3(-0.975,-0.65) 4(0.975,-0.65) 5(0.975,0) 6(0.975,0.65)
  rect 0.9x0.625 smd paste-0.025: 7(0,0.488) 8(0,-0.488)
  silkscreen extent -1.15,-1.15 1.15,1.15, body extent -1.05,-1.05 1.05,1.05, height 0.8
FCC_disclaimer [mil]
Fiducial10-20 [mm]
  round 1 smd mask+0.5: 1(0,0)
  Top Layer keep-out circle w1.178: c0,0 r0.5
Keystone5010 [mil] "Keystone Multipurpose loops"
  round 87 hole 63: 1(0,0)
  silkscreen extent -70,-70 70,70, body extent -63,-63 63,62, height 319
Keystone5011 [mil] "Keystone Multipurpose loops"
  round 87 hole 63: 1(0,0)
  silkscreen extent -70,-70 70,70, body extent -63,-63 63,62, height 319
On-Shore_OSTVN02A150 [mm] "Terminal Block, 2.54mm, 2-pole, Brass, TH"
  rect 1.8x1.8 hole 1.3: 1(-1.27,0)
  round 1.8 hole 1.3: 2(1.27,0)
  silkscreen extent -3.1,-3.25 2.77,3.25, body extent -2.77,-3.25 2.77,3.25, height 8.51
PWP0016J_N [mm] "TSOP, 16-Leads, Body 5x4.4mm, Pitch 0.65mm, Exposed Pad, IPC Medium Density"
  rrect22% 1.4x0.45 smd: 1(-2.95,2.275) 2(-2.95,1.625) 3(-2.95,0.975) 4(-2.95,0.325) 5(-2.95,-0.325) 6(-2.95,-0.975) 7(-2.95,-1.625) 8(-2.95,-2.275) 9(2.95,-2.275) 10(2.95,-1.625) 11(2.95,-0.975) 12(2.95,-0.325) 13(2.95,0.325) 14(2.95,0.975) 15(2.95,1.625) 16(2.95,2.275)
  rrect6% 3.4x5 smd paste-1.7 mask-1.7: 17(0,0)
  rrect4% 2.46x3.55 on Top Paste: 17(0,0)
  rrect4% 2.46x3.55 on Top Solder: 17(0,0)
  silkscreen extent -3.55,-2.55 1.5,2.75, body extent -3.2,-2.5 3.2,2.5, height 1.13
RGY0020C [mm] "VQFN-20"
  rrect40% 0.25x0.6 smd: 1(-0.75,2.15) 10(-0.75,-2.15) 11(0.75,-2.15) 20(0.75,2.15)
  rrect40% 0.6x0.25 smd: 2(-1.65,1.75) 3(-1.65,1.25) 4(-1.65,0.75) 5(-1.65,0.25) 6(-1.65,-0.25) 7(-1.65,-0.75) 8(-1.65,-1.25) 9(-1.65,-1.75) 12(1.65,-1.75) 13(1.65,-1.25) 14(1.65,-0.75) 15(1.65,-0.25) 16(1.65,0.25) 17(1.65,0.75) 18(1.65,1.25) 19(1.65,1.75)
  rrect5% 2.2x3.2 smd paste-1.4: 21(0,0)
  Top Layer region: -0.375,-1.6 -1.05,-1.6 -1.069,-1.596 -1.085,-1.585 -1.096,-1.569 -1.1,-1.55 -1.1,-1.55 -1.1,1.55 -1.096,1.569 -1.085,1.585 -1.069,1.596 -1.05,1.6 -1.05,1.6 -0.375,1.6 -0.375,2.4 -0.371,2.419 -0.36,2.435 -0.344,2.446 -0.325,2.45 -0.325,2.45 -0.175,2.45 -0.156,2.446 -0.14,2.435 -0.129,2.419 -0.125,2.4 -0.125,2.4 -0.125,2.1 0.125,2.1 0.125,2.4 0.129,2.419 0.14,2.435 0.156,2.446 0.175,2.45 0.175,2.45 0.325,2.45 0.344,2.446 0.36,2.435 0.371,2.419 0.375,2.4 0.375,2.4 0.375,1.6 1.05,1.6 1.069,1.596 1.085,1.585 1.096,1.569 1.1,1.55 1.1,1.55 1.1,-1.55 1.096,-1.569 1.085,-1.585 1.069,-1.596 1.05,-1.6 1.05,-1.6 0.375,-1.6 0.375,-2.4 0.371,-2.419 0.36,-2.435 0.344,-2.446 0.325,-2.45 0.325,-2.45 0.325,-2.45 0.175,-2.45 0.175,-2.45 0.156,-2.446 0.14,-2.435 0.129,-2.419 0.125,-2.4 0.125,-2.4 0.125,-2.1 -0.125,-2.1 -0.125,-2.4 -0.129,-2.419 -0.14,-2.435 -0.156,-2.446 -0.175,-2.45 -0.175,-2.45 -0.175,-2.45 -0.325,-2.45 -0.325,-2.45 -0.344,-2.446 -0.36,-2.435 -0.371,-2.419 -0.375,-2.4 -0.375,-2.4
  body extent -1.75,-2.25 1.75,2.25, height 1
SMA [mm] "Molded Diode, 2-Leads, Body 4.3x2.6mm, IPC Medium Density, based on OnSemi component dimensions and land pattern"
  rect 2x2 smd: 1(-2,0) 2(2,0)
  silkscreen extent -3.66,-1.57 2.79,1.57, body extent -2.6,-1.3 2.6,1.3, height 2.42
SOD-123 [mm] "On Semi recommended land pattern"
  rect 0.915x1.22 smd: 1(-1.637,0) 2(1.637,0)
  silkscreen extent -2.74,-1.17 2.03,1.17, body extent -1.93,-0.9 1.93,0.9, height 1.35
SOD-323-Bi [mm] "SOD323, 2-Leads, Body 1.9x1.45mm, No Polarity Mark"
  rect 0.6x0.6 smd paste-0.05: 1(-1.1,0) 2(1.1,0)
  silkscreen extent -1.53,-0.77 1.53,0.77, body extent -1.27,-0.65 1.27,0.65, height 1.02
SOT-23 [mm] "SOT23, 3-Leads, Body 2.9x1.3mm, Pitch 0.95mm, Lead Span 2.5mm, IPC Medium Density"
  rrect50% 1x0.6 smd: 1(-1.2,0.95) 2(-1.2,-0.95) 3(1.2,0)
  silkscreen extent -1.63,-1.5 0.7,1.5, body extent -1.16,-1.45 1.21,1.45, height 1
SW_B3U-1000P [mm] "OMRON"
  rect 0.8x1.7 smd: 1(-1.7,0) 2(1.7,0)
  silkscreen extent -1.5,-1.25 1.5,1.25, body extent -1.5,-1.25 1.5,1.25, height 1.75
TE_5747840-5 [mm] "D-Sub, 2.74mm, 9 Position, R/A, TH"
  rrect50% 1.55x1.55 hole 1.04: 1(-5.48,10.954)
  round 1.55 hole 1.04: 2(-2.74,10.954) 3(0,10.954) 4(2.74,10.954) 5(5.48,10.954) 6(-4.11,8.114) 7(-1.37,8.114) 8(1.37,8.114) 9(4.11,8.114)
  round 3.7 hole 3.17: 10(12.495,9.534) 11(-12.495,9.534)
  silkscreen extent -15.52,0.2 15.52,12.71, body extent -15.52,-5.89 15.52,12.71, height 12.55
TI_Stacked_Overlay_Small [mil]
  silkscreen extent -418,-98 418,98
TP_SM_1MM [mm] "1mm Test Point, SMT"
  round 1 smd paste-0.5: 1(0,0)
TSW-102-07-G-S [mm] "Samtec 100mil, 1x2, 230 mil above insulator"
  rrect50% 1.65x1.65 hole 1.016: 1(-1.27,0)
  round 1.65 hole 1.016: 2(1.27,0)
  body extent -2.54,-1.27 2.54,1.27, height 8.38
TSW-103-07-G-S [mm] "Samtec 100mil, 1x3, 230 mil above insulator"
  rrect50% 1.65x1.65 hole 1.016: 1(-2.54,0)
  round 1.65 hole 1.016: 2(0,0) 3(2.54,0)
  body extent -3.81,-1.27 3.81,1.27, height 8.38
TSW-106-07-G-S [mm] "Samtec 100mil, 1x6, 230 mil above insulator"
  rrect50% 1.65x1.65 hole 1.016: 1(-6.35,0)
  round 1.65 hole 1.016: 2(-3.81,0) 3(-1.27,0) 4(1.27,0) 5(3.81,0) 6(6.35,0)
  body extent -7.62,-1.27 7.62,1.27, height 8.38
WE-TPC_2828 [mm] "WURTH"
  rect 1x3.2 smd: 1(-1.1,0) 2(1.1,0)
  body extent -1.5,-1.5 1.5,1.5, height 3
WEEE_Minimum [mil] "WEEElie bin"
  silkscreen extent -95,-172 99,104
WL-SMCW_Blue [mm] "SMD, 2-Leads, Body 1.6x0.8mm"
  rect 0.8x0.8 smd: 1(-0.8,0) 2(0.8,0)
  silkscreen extent -1.9,-0.8 1.2,0.8, body extent -0.85,-0.45 0.85,0.45, height 0.8
WL-SMCW_GREEN [mm] "WURTH"
  rect 0.8x0.8 smd: 1(-0.8,0) 2(0.8,0)
  silkscreen extent -1.9,-0.8 1.2,0.8, body extent -0.85,-0.45 0.85,0.45, height 0.8
WL-SMCW_RED [mm] "WURTH"
  rect 0.8x0.8 smd: 1(-0.8,0) 2(0.8,0)
  silkscreen extent -1.9,-0.8 1.2,0.8, body extent -0.85,-0.45 0.85,0.45, height 0.8
WL-SMCW_YELLOW [mm] "WURTH"
  rect 0.8x0.8 smd: 1(-0.8,0) 2(0.8,0)
  silkscreen extent -1.9,-0.8 1.2,0.8, body extent -0.85,-0.45 0.85,0.45, height 0.8
Wurth_60900213421 [mil] "Shunt, 2.54mm, Black"
  round 1 on Mech3: 0(0,0)
  body extent -98,-48 98,48, height 338
XTAL_NX2016SA [mm] "2.0 x 1.6 x 0.45mm Crystal"
  rect 0.85x0.75 smd mask+0.076: 1(-0.675,-0.525) 2(0.675,-0.525) 3(0.675,0.525) 4(-0.675,0.525)
  silkscreen extent -1.2,-1.1 1.2,1.1, body extent -1,-0.8 1,0.8, height 0.51

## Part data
C1 C7 C12 C13 C20 C24 C26 C29: library part CMP-0007078-4, "CAP, CERM, 0.1 uF, 50 V, +/- 10%, X7R, AEC-Q200 Grade 1, 0603", Cap_Case=0603, Manufacturer=TDK, Supplier Part Number 1=445-5666-1-ND, TempCo=X7R, Tolerance_%=10%, Value1="0.0296 ohm", Value2=50V, ValueDisplayed=0.1uF
C2 C23 C28: library part CMP-0007508-5, "CAP, CERM, 1 uF, 50 V, +/- 10%, X7R, 0603", Cap_Case=0603, Manufacturer="Taiyo Yuden", Supplier Part Number 1=587-3247-1-ND, TempCo=X7R, Tolerance_%=10%, Value1=Unknown, Value2=50V, ValueDisplayed=1uF
C3 C25: library part CMP-0008802-2, "CAP, CERM, 10 uF, 50 V, +/- 10%, X7R, 1206", Cap_Case=1206, Manufacturer=Samsung, Supplier Part Number 1=1276-6767-1-ND, TempCo=X7R, Tolerance_%=10%, Value1=Unknown, Value2=50V, ValueDisplayed=10uF
C4 C5 C6: library part CMP-0007081-4, "CAP, CERM, 1000 pF, 100 V, +/- 10%, X7R, AEC-Q200 Grade 1, 0603", Cap_Case=0603, Manufacturer=TDK, Supplier Part Number 1=445-5806-1-ND, TempCo=X7R, Tolerance_%=10%, Value1="1.97137 ohm", Value2=100V, ValueDisplayed=1000pF
C8 C9: library part CMP-0007074-4, "CAP, CERM, 10 pF, 50 V, +/- 5%, C0G/NP0, 0603", Cap_Case=0603, Manufacturer=TDK, Supplier Part Number 1=445-12387-1-ND, TempCo=C0G/NP0, Tolerance_%=5%, Value1=Unknown, Value2=50V, ValueDisplayed=10pF
C10: library part CMP-0006776-4, "CAP, CERM, 220 pF, 50 V, +/- 1%, C0G/NP0, 0603", Cap_Case=0603, Manufacturer=AVX, Supplier Part Number 1=478-3719-1-ND, TempCo=C0G/NP0, Tolerance_%=1%, Value1="0.083 ohm", Value2=50V, ValueDisplayed=220pF
C11: library part CMP-0006746-5, "CAP, CERM, 4700 pF, 100 V, +/- 10%, X7R, 0603", Cap_Case=0603, Manufacturer=AVX, Supplier Part Number 1=478-1203-1-ND, TempCo=X7R, Tolerance_%=10%, Value1="0.136 ohm", Value2=100V, ValueDisplayed=4700pF
C14 C17: library part CMP-0860185-1, "CAP, CERM, 8 pF, 50 V,+/- 6.25%, C0G/NP0, 0402", Cap_Case=0402, Manufacturer=Yageo, TempCo=C0G/NP0, Tolerance_%=6.25%, Value2=50V, ValueDisplayed=8pF
C15: library part CMP-0008484-2, "CAP, CERM, 0.01 uF, 100 V, +/- 5%, X7R, 1206", Cap_Case=1206, Manufacturer=AVX, Supplier Part Number 1=478-3783-1-ND, TempCo=X7R, Tolerance_%=5%, Value1="0.119 ohm", Value2=100V, ValueDisplayed=0.01uF
C16 C18: library part CMP-0006763-4, "CAP, CERM, 100 pF, 50 V, +/- 5%, C0G/NP0, 0603", Cap_Case=0603, Manufacturer=AVX, Supplier Part Number 1=478-1175-1-ND, TempCo=C0G/NP0, Tolerance_%=5%, Value1="0.119 ohm", Value2=50V, ValueDisplayed=100pF
C19: library part CMP-0006924-4, "CAP, CERM, 0.33 uF, 16 V, +/- 10%, X7R, 0603", Cap_Case=0603, Manufacturer=Kemet, Supplier Part Number 1=399-4916-1-ND, TempCo=X7R, Tolerance_%=10%, Value1=Unknown, Value2=16V, ValueDisplayed=0.33uF
C21: library part CMP-0007995-2, "CAP, CERM, 10 uF, 16 V, +/- 10%, X7R, 0805", Cap_Case=0805, Manufacturer="Samsung Electro-Mechanics", TempCo=X7R, Tolerance_%=10%, Value1=Unknown, Value2=16V, ValueDisplayed=10uF
C22 C27: library part CMP-0078542-1, "CAP, CERM, 10 µF, 16 V,+/- 10%, X7R, 1206", Cap_Case=1206, Manufacturer=Kemet, Supplier Part Number 1=399-3525-1-ND, TempCo=X7R, Tolerance_%=10%, Value2=16V, ValueDisplayed=10µF
C30 C31 C32: library part CMP-0079154-1, "CAP, CERM, 1 µF, 16 V,+/- 10%, X7R, AEC-Q200 Grade 1, 0603", Cap_Case=0603, Manufacturer=MuRata, Supplier Part Number 1=490-12657-1-ND, TempCo=X7R, Tolerance_%=10%, Value2=16V, ValueDisplayed=1µF
D1: library part CMP-0028550-2, "Diode, Schottky, 40 V, 1 A, SMA", Manufacturer="ON Semiconductor", Value1=1A, Value2=0.55V
D2: library part CMP-0076974-2, "Diode, Switching, 100 V, 0.15 A, SOD-123", Manufacturer="Micro Commercial Components", Value1=0.15A, Value2=1.25V
D3: library part CMP-0005515-4, "Diode, Zener, 30 V, 3 W, SMA", Manufacturer="Micro Commercial Components", Power_W=3W
D4 D5 D6 D10: library part CMP-0002905-2, "LED, Green, SMD", Color=Green, Manufacturer="Wurth Elektronik", Value1=W, Value2=3.2V
D7: library part CMP-0005821-3, "Diode, TVS, Bi, 15 V, SOD-323", Manufacturer="NXP Semiconductor", Value1=160W
D8: library part CMP-0005920-3, "Diode, TVS, Bi, 24 V, 70 Vc, AEC-Q101, SOT-23", Manufacturer="NXP Semiconductor", Value1=200W
D9: library part CMP-0002892-3, "LED, Yellow, SMD", Color=yellow, Manufacturer="Wurth Elektronik", Value1=W, Value2=2V
D11: library part CMP-0002946-3, "LED, Blue, SMD", Color=Blue, Manufacturer="Wurth Elektronik", Power_TotalModule=105mW, Value1=0.105W, Value2=3.2V
D12: library part CMP-0002947-3, "LED, Red, SMD", Color=Red, Manufacturer="Wurth Elektronik", Power_TotalModule=72mW, Value1=0.072W, Value2=2V
FID1 FID2 FID3: library part CMP-0077181-1, "Fiducial mark.  There is nothing to buy or mount.", Manufacturer=N/A
J1 J4 J15: library part CMP-0075407-2, "Header, 100mil, 3x1, Gold, TH", Color=Black, Current_A=6.3A, Manufacturer=Samtec, Supplier Part Number 1=SAM1029-03-ND, Voltage_V=550V
J2: library part CMP-0075114-1, "Power Jack, 2mm, R/A, TH", Color=Black, Manufacturer="CUI Inc.", Supplier Part Number 1=CP-037AH-ND
J3 J6 J9 J10 J11 J12: library part CMP-0075405-2, "Header, 100mil, 2x1, Gold, TH", Color=Black, Current_A=6.3A, Manufacturer=Samtec, Supplier Part Number 1=SAM1029-02-ND, Voltage_V=550V
J5: library part CMP-0075076-1, "Terminal Block, 2.54mm, 2x1, Brass, TH", Manufacturer="On-Shore Technology", Supplier Part Number 1=ED10561-ND
J7: library part CMP-0054938-4, "D-Sub, 2.74mm, 9 Position, R/A, TH", Color=Black, Manufacturer="TE Connectivity", Supplier Part Number 1=A32093-ND
J8: library part CMP-0075413-2, "Header, 100mil, 6x1, Gold, TH", Color=Black, Current_A=6.3A, Manufacturer=Samtec, Supplier Part Number 1=SAM1029-06-ND, Voltage_V=550V
J13: library part CMP-0078266-4, "Receptacle, 2.54mm, 10x2, Tin, TH", Alternate Manufacturer="Major League Electronics", Alternate PartNumber=CRD-081413-A-G, Manufacturer=Samtec, Supplier Part Number 1=SAM1204-10-ND
J14: library part CMP-0003837-4, "Receptacle, 2.54mm, 10x2, Tin, TH", Alternate Manufacturer="Major League Electronics", Alternate PartNumber=CRD-081413-A-G, Manufacturer=Samtec, Supplier Part Number 1=SAM1204-10-ND
L1: library part CMP-0001617-1, "Inductor, Wirewound, Ferrite, 4.7 µH, 1.65 A, 0.08 ohm, AEC-Q200 Grade 0, SMD", Manufacturer=TDK, Supplier Part Number 1=495-2665-1-ND, Value1="0.08 ohm", Value2=1.65A, ValueDisplayed=4.7µH
L2: library part CMP-0062430-2, "Inductor, Ferrite, 100 uH, 0.15 A, 2 ohm, SMD", Manufacturer=TDK, Supplier Part Number 1=445-3959-1-ND, Value1="2 ohm", Value2=0.15A, ValueDisplayed=100uH
L3: library part CMP-0063757-1, "Inductor, Shielded Drum Core, Ferrite, 10 uH, 1 A, 0.17 ohm, SMD", Manufacturer="Wurth Elektronik", Supplier Part Number 1=732-2617-1-ND, Value1="0.17 ohm", Value2=1A, ValueDisplayed=10uH
Logo1: library part CMP-0074838-1, "Texas Instrument Corporate Signature"
Logo3: library part CMP-0074847-1, "FCC_disclaimer"
LOGO4: library part CMP-0074844-1
Logo5: library part CMP-0074769-1
Q1 Q2 Q3 Q4 Q5: library part CMP-0000208-1, "MOSFET, 2-CH, N-CH, 20 V, 6.7 A, DQK0006B (WSON-6)", Alternate Manufacturer=None, Manufacturer="Texas Instruments", Supplier Part Number 1=296-40010-1-ND, Value1=0.02, Value2="4.2 nC"
R1: library part CMP-0020833-2, "RES, 0, 1%, 0.5 W, 0805", Manufacturer=Keystone, Power_W=500mW, Supplier Part Number 1=36-5106CT-ND, TempCo=ppm/C, Tolerance_%=1%, Value2=0.5W, Value_Code=0
R2 R3 R5 R6 R8 R19 R23 R24 R26 R27 R29 R31 R32 R34 R38 R47 R61 R62: library part CMP-0078669-1, "RES, 10.0 k, 1%, 0.063 W, 0402", Manufacturer="Yageo America", Power_W=63mW, Supplier Part Number 1=311-10.0KLRCT-ND, TempCo="100 ppm/C", Tolerance_%=1%, Value2=0.063W, Value_Code=10k0, ValueDisplayed=10.0k
R4 R18 R33: library part CMP-0026740-1, "RES, 4.99 k, 1%, 0.063 W, 0402", Manufacturer="Yageo America", Power_W=63mW, Supplier Part Number 1=311-4.99KLRCT-ND, TempCo="100 ppm/C", Tolerance_%=1%, Value2=0.063W, Value_Code=4k99, ValueDisplayed=4.99k
R7: library part CMP-0026071-3, "RES, 1.00 k, 1%, 0.063 W, AEC-Q200 Grade 0, 0402", Manufacturer=Vishay-Dale, Power_W=63mW, Supplier Part Number 1=541-1.00KLCT-ND, TempCo="100 ppm/C", Tolerance_%=1%, Value2=0.063W, Value_Code=1k00, ValueDisplayed=1.00k
R9 R25 R45: library part CMP-0026745-1, "RES, 100 k, 1%, 0.063 W, 0402", Manufacturer="Samsung Electro-Mechanics", Power_W=63mW, Supplier Part Number 1=1276-3432-1-ND, TempCo="100 ppm/C", Tolerance_%=1%, Value2=0.063W, Value_Code=100k
R10 R14: library part CMP-0018748-3, "RES, 0, 5%, 0.25 W, AEC-Q200 Grade 0, 1206", Manufacturer=Panasonic, Power_W=250mW, Supplier Part Number 1=P0.0ECT-ND, TempCo="600 ppm/C", Tolerance_%=5%, Value2=0.25W, Value_Code=0000, ValueDisplayed=0
R11 R12: library part CMP-0023213-5, "RES, 60.4, 1%, 0.1 W, 0603", Manufacturer=Yageo, Power_W=100mW, Supplier Part Number 1=311-60.4HRCT-ND, TempCo="100 ppm/C", Tolerance_%=1%, Value2=0.1W, Value_Code=60R4, ValueDisplayed=60.4
R13 R35: library part CMP-0026695-1, "RES, 3.30 k, 1%, 0.1 W, AEC-Q200 Grade 0, 0402", Manufacturer=Panasonic, Power_W=100mW, Supplier Part Number 1=P3.30KLCT-ND, TempCo="100 ppm/C", Tolerance_%=1%, Value2=0.1W, Value_Code=3k30, ValueDisplayed=3.30k
R15: library part CMP-0026660-1, "RES, 1.00 M, 1%, 0.1 W, 0402", Manufacturer=Panasonic, Power_W=100mW, Supplier Part Number 1=P1.00MLCT-ND, TempCo="100 ppm/C", Tolerance_%=1%, Value2=0.1W, Value_Code=1M00, ValueDisplayed=1.00M
R16 R58: library part CMP-0026298-2, "RES, 33.2 k, 1%, 0.063 W, AEC-Q200 Grade 0, 0402", Manufacturer=Vishay-Dale, Power_W=63mW, Supplier Part Number 1=541-33.2KLCT-ND, TempCo="100 ppm/C", Tolerance_%=1%, Value2=0.063W, Value_Code=33k2, ValueDisplayed=33.2k
R17 R20 R21 R36 R39 R40 R41 R42 R44 R46 R48 R49 R50 R51 R52 R53 R54 R55 R57 R59 R60: library part CMP-0027004-2, "RES, 0, 5%, 0.063 W, 0402", Manufacturer="Yageo America", Power_W=63mW, Supplier Part Number 1=311-0.0JRCT-ND, TempCo="200 ppm/C", Tolerance_%=5%, Value2=0.063W, Value_Code=0000, ValueDisplayed=0
R22 R28: library part CMP-0026725-1, "RES, 1.00 k, 1%, 0.0625 W, 0402", Manufacturer="Yageo America", Power_W=62.5mW, Supplier Part Number 1=311-1.00KLRCT-ND, TempCo="100 ppm/C", Tolerance_%=1%, Value2=0.0625W, Value_Code=1k00, ValueDisplayed=1.00k
R30: library part CMP-0026469-2, "RES, 5.90 k, 1%, 0.063 W, AEC-Q200 Grade 0, 0402", Manufacturer=Vishay-Dale, Power_W=63mW, Supplier Part Number 1=541-5.90KLCT-ND, TempCo="100 ppm/C", Tolerance_%=1%, Value2=0.063W, Value_Code=5k90, ValueDisplayed=5.90k
R37 R43: library part CMP-0026088-3, "RES, 1.50 k, 1%, 0.063 W, AEC-Q200 Grade 0, 0402", Manufacturer=Vishay-Dale, Power_W=63mW, Supplier Part Number 1=541-1.50KLCT-ND, TempCo="100 ppm/C", Tolerance_%=1%, Value2=0.063W, Value_Code=1k50, ValueDisplayed=1.50k
R56: library part CMP-0026050-3, "RES, 17.4 k, 1%, 0.063 W, AEC-Q200 Grade 0, 0402", Manufacturer=Vishay-Dale, Power_W=63mW, Supplier Part Number 1=541-17.4KLCT-ND, TempCo="100 ppm/C", Tolerance_%=1%, Value2=0.063W, Value_Code=17k4, ValueDisplayed=17.4k
S1 S2: library part CMP-0002150-2, "SWITCH TACTILE SPST-NO 0.05A 12V", CurrentRating_mA=50A, Manufacturer="Omron Electronic Components", Supplier Part Number 1=SW1020CT-ND
SH-J1 SH-J2 SH-J3 SH-J4 SH-J5 SH-J6 SH-J7 SH-J8 SH-J9: library part CMP-0003761-2, "Shunt, 2.54mm, Gold, Black", Manufacturer="Wurth Elektronik", Supplier Part Number 1=732-2678-ND
TP1: library part CMP-0055147-1, "Test Point, Multipurpose, Red, TH", Color=Red, Manufacturer=Keystone, Supplier Part Number 1=36-5010-ND
TP2: library part CMP-0055148-1, "Test Point, Multipurpose, Black, TH", Color=Black, Manufacturer=Keystone, Supplier Part Number 1=36-5011-ND
TP3 TP4 TP5: library part CMP-0003825-1, "1mm Test Point, SMT", Manufacturer=Any
U1: library part CMP-0079160-1, "Fault Protected Local Interconnect Network (LIN) Transceiver with Dominant State Timeout, D0008A (SOIC-8)", Alternate Manufacturer="Texas Instruments", Alternate PartNumber=TLIN2029DRQ1
U2: library part CMP-0065224-7, "CAN-FD Controller with Integrated Transceiver, RGY0020A (VQFN-20)", Alternate Manufacturer="Texas Instruments", Alternate PartNumber=TCAN4550RGYQ1, Operating Temperature Range="-40 to 125 C", Rating=Automotive
U3: library part CMP-0073734-2, "Dual-Channel Antenna LDO With Current Sense, PWP0016J (TSSOP-16)", Alternate Manufacturer="Texas Instruments"
U4: library part CMP-0051651-2, "Low Power, 1.8/2.5/3.3-V Input, 3.3-V CMOS Output, Single Inverter Gate, DCK0005A, LARGE T&R", F @ Nom Voltage(Max)(Mhz)=190, Generic Part Number=SN74AUP1T04, ICC @ Nom Voltage(Max)(mA)=0.0009, Manufacturer="Texas Instruments", Operating Temperature Range(C)="-40 to 85", Rating=Catalog, tpd @ Nom Voltage(Max)(ns)=9.8,8.5,7.8, Voltage(Nom)(V)=1.8,2.5,3.3
Y1: library part CMP-0085289-1, "Crystal, 40 MHz, 10 ppm, 8 pF, AEC-Q200 Grade 0, SMD", Frequency_Fixed=40MHz, Frequency Stability="25 ppm", Frequency Tolerance="10 ppm", Load Capacitance="8 pF", Manufacturer=NDK
ZZ2: library part CMP-0077236-1
ZZ3: library part CMP-0077237-1
ZZ4: library part CMP-0077238-1

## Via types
v1: diameter 28, hole 10, Top Layer to Bottom Layer, tented both sides, 114 vias
v2: diameter 19.68, hole 7.87, Top Layer to Bottom Layer, tented both sides, 12 vias
v3: diameter 19.68, hole 7.87, Top Layer to Bottom Layer, tented bottom, 7 vias

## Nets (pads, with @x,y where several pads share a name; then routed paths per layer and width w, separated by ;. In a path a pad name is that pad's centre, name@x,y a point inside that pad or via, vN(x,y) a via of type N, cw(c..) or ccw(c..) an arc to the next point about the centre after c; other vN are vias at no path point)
3V3: C7.1 C13.1 C22.2 C23.1 C24.1 J11.1 R6.2 R8.2 R22.2 R23.2 R29.2 R31.2 R61.2 R62.2 TP3.1 U2.17 U3.14 U4.5 | length 201.8
  Top Layer w10: v1(910,1850) R6.2@910,1880 ; v1(1783,1318) 1800,1318 1820,1338 R61.2@1820,1365.65 ; R31.2@1864,1791 1865,1790 v1(1865,1766) ; R8.2@1864,2490 1865,2491 v1(1865,2515) ; v1(1865,1966) R23.2@1865,1991 ; v1(1865,2171.79) R62.2@1865,2194.79
  other v1: 837,1203 1475,1500
3V3_LED: Q2.2 R8.1 | length 48
  Top Layer w10: R8.1@1864,2451 R8.1@1865,2450 Q2.2@1911.61,2450
3V3_LEDA: D5.2 R3.1 | length 61.2
  Top Layer w10: R3.1@2206.5,2460 2206.5,2399.5 D5.2@2207,2399
3V3_LEDC: D5.1 Q2.6 Q2.7 | length 261.7
  Top Layer w10: Q2.7@1949,2468 1956.59,2475.59 Q2.6@1988.39,2475.59 ; Q2.6@1987,2475 2092,2475 2105,2462 2105,2408 2113,2400 D5.1@2143.5,2400
3V3_LP: J11.2 J14.1
5V0: C27.2 C28.1 C29.1 J12.2 R2.2 R3.2 R4.2 R18.2 R19.2 R24.2 R26.2 R28.2 R32.2 R33.2 R34.1 TP4.1 U3.16 | length 293.4
  Top Layer w10: v1(2035,1766) R32.2@2035,1791 ; v1(2035,1966) R24.2@2035,1991 ; v1(2035,2172) 2035,2196 2034,2197 R26.2@2035,2197 ; v1(2136.5,1460) 2166,1460 R33.2@2167,1459 ; v1(2136.5,1660) R28.2@2166,1660 ; v1(2136.5,2060) R19.2@2166.5,2060 2167,2060 R19.2@2168,2059 ; v1(2136.5,2260) 2166,2260 R4.2@2167,2259 ; v1(2136.5,2460) 2165,2460 R3.2@2166,2459 ; v1(2136.5,2660) 2165,2660 R2.2@2166,2661 ; v1(2137.15,1860.01) R18.2@2166.5,1860 ; R2.2@2166,2660 R2.2@2166.5,2660.5 ; R33.2@2166.5,1461.5 R33.2@2167,1461 ; R28.2@2166.5,1660.5 R28.2@2167,1660 ; R4.2@2166.5,2260.5 R4.2@2167,2260 ; R18.2@2167,1859 2166.5,1859.5 R18.2@2166.5,1860 ; R18.2@2167,1860 R18.2@2166.5,1860
5V0_LEDA: D10.2 R19.1 | length 61
  Top Layer w10: R19.1@2206.5,2060 2206.5,2002.5 D10.2@2209,2000
5V_LP: J12.1 J14.21 | length 5
  Bottom Layer w15: J14.21@345,1100 J14.21@350,1100
CAN_GPIO1: J14.5 R48.2 | length 1971.4
  Top Layer w10: J14.5@250,700 J14.5@262,700 ; R48.2@1820,1445.65 1844.35,1445.65 v1@1845,1445
  Bottom Layer w10: J14.5@262,700 313,649 955,649 1635,1329 1728.35,1329 v1(1845,1445.65)
CAN_GPO2: J13.32 R54.2 | length 2190.5
  Top Layer w10: R54.2@1822,1725 1832,1725 2013,1544 2013,1474.28 2217.87,1269.4 2217.87,1269.13 2218,1269 2218,276 2084,142 1905,142 1873,174 1873,223 J13.32@1950,300
CAN_INH: R60.2 U2.15 | length 904.8
  Top Layer w10: R60.2@700,1705 756,1705 849,1612 1159,1612 1215.51,1555.49 U2.15@1542.91,1555.49
CAN_nINT: J13.31 R55.2 | length 1829.1
  Top Layer w10: R55.2@1820,1685 1841,1685 1993,1533 1993,1469 2200,1262 2200,329 2122,251 2001,251 J13.31@1950,200
CAN_nWRKQ: J13.33 R53.2 | length 1284.9
  Top Layer w10: R53.2@1819,1406 1923,1406 2108,1221 2108,679 2079,650 2024,650 2000,626 2000,449 1951,400 J13.33@1950,400
CAN_RST: C18.1 J10.1 R25.2 R46.2 S2.2 U2.19 | length 898.8
  Top Layer w10: C18.1@1050,1180 1050,1264 1065,1279 S2.2@1088,1279 ; S2.2@1086.93,1280 1086.93,1324.93 1093,1331 1417,1331 1430,1344 R25.2@1430,1385 1495,1385 1544,1434 U2.19@1544,1477 ; J10.1@1354,1279 J10.1@1355,1280 J10.1@1356,1280 ; J10.1@1356,1278 J10.1@1356,1280 ; 1356,1328 J10.1@1356,1280 ; R46.2@1460,1280 J10.1@1356,1280
CANH: L2.1 R10.1 U2.11 | length 136.9
  Top Layer w10: R10.1@1558.66,1758.91 1558.66,1689.34 1578,1670 U2.11@1578,1630
CANH_BUS: D8.2 J6.1 J7.7 J8.4 L2.4 R10.2 | length 1310.2
  Top Layer w10: J6.1@1532,2005 1558.66,1978.34 R10.2@1558.66,1873.09 ; J6.1@1532.79,2005 1466,2071.79 1466,2087 1466,2427 1570.47,2531.47 D8.2@1570.47,2537.24 1570.47,2766.53 J8.4@1559,2778 ; J8.4@1557.87,2780 1557.87,2832.87 1605,2880 J7.7@1605,3079
CANL: L2.2 R14.1 U2.10 | length 133.2
  Top Layer w10: U2.10@1637,1634 1637,1671 1657.09,1691.09 R14.1@1657.09,1758.91
CANL_BUS: D8.1 J7.2 J8.3 J9.2 L2.3 R14.2 | length 1180.4
  Top Layer w10: R14.2@1657.09,1873.09 1657.09,1980.09 J9.2@1680,2003 ; J8.3@1657.87,2780 1657.87,2965.87 J7.2@1659,2967 ; J8.3@1659,2781 1645.28,2767.28 D8.1@1645.28,2537.24 1645.28,2527.72 1750,2423 1750,2073.79 J9.2@1681.21,2005
CRYSTAL1: C14.1 R17.2 Y1.1 | length 241.6
  Top Layer w10: C14.1@1525,1274 1505,1274 1493,1286 1493,1334 1529,1370 R17.2@1578.35,1370 ; C14.1@1525,1275 1580,1275 Y1.1@1581,1274
CRYSTAL3: C17.1 R20.2 Y1.3 | length 163.8
  Top Layer w10: Y1.3@1633,1314 1634,1315 C17.1@1690.75,1315 ; R20.2@1637.4,1370 1686,1370 1691,1365 C17.1@1691,1315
